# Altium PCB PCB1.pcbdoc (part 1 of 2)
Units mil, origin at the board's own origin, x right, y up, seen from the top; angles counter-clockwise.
Board outline 29590.16 x 26896.25 mil, 2 copper layers (Top Layer, Bottom Layer); 414 components, 328 nets, 1399 pads, 0 vias.
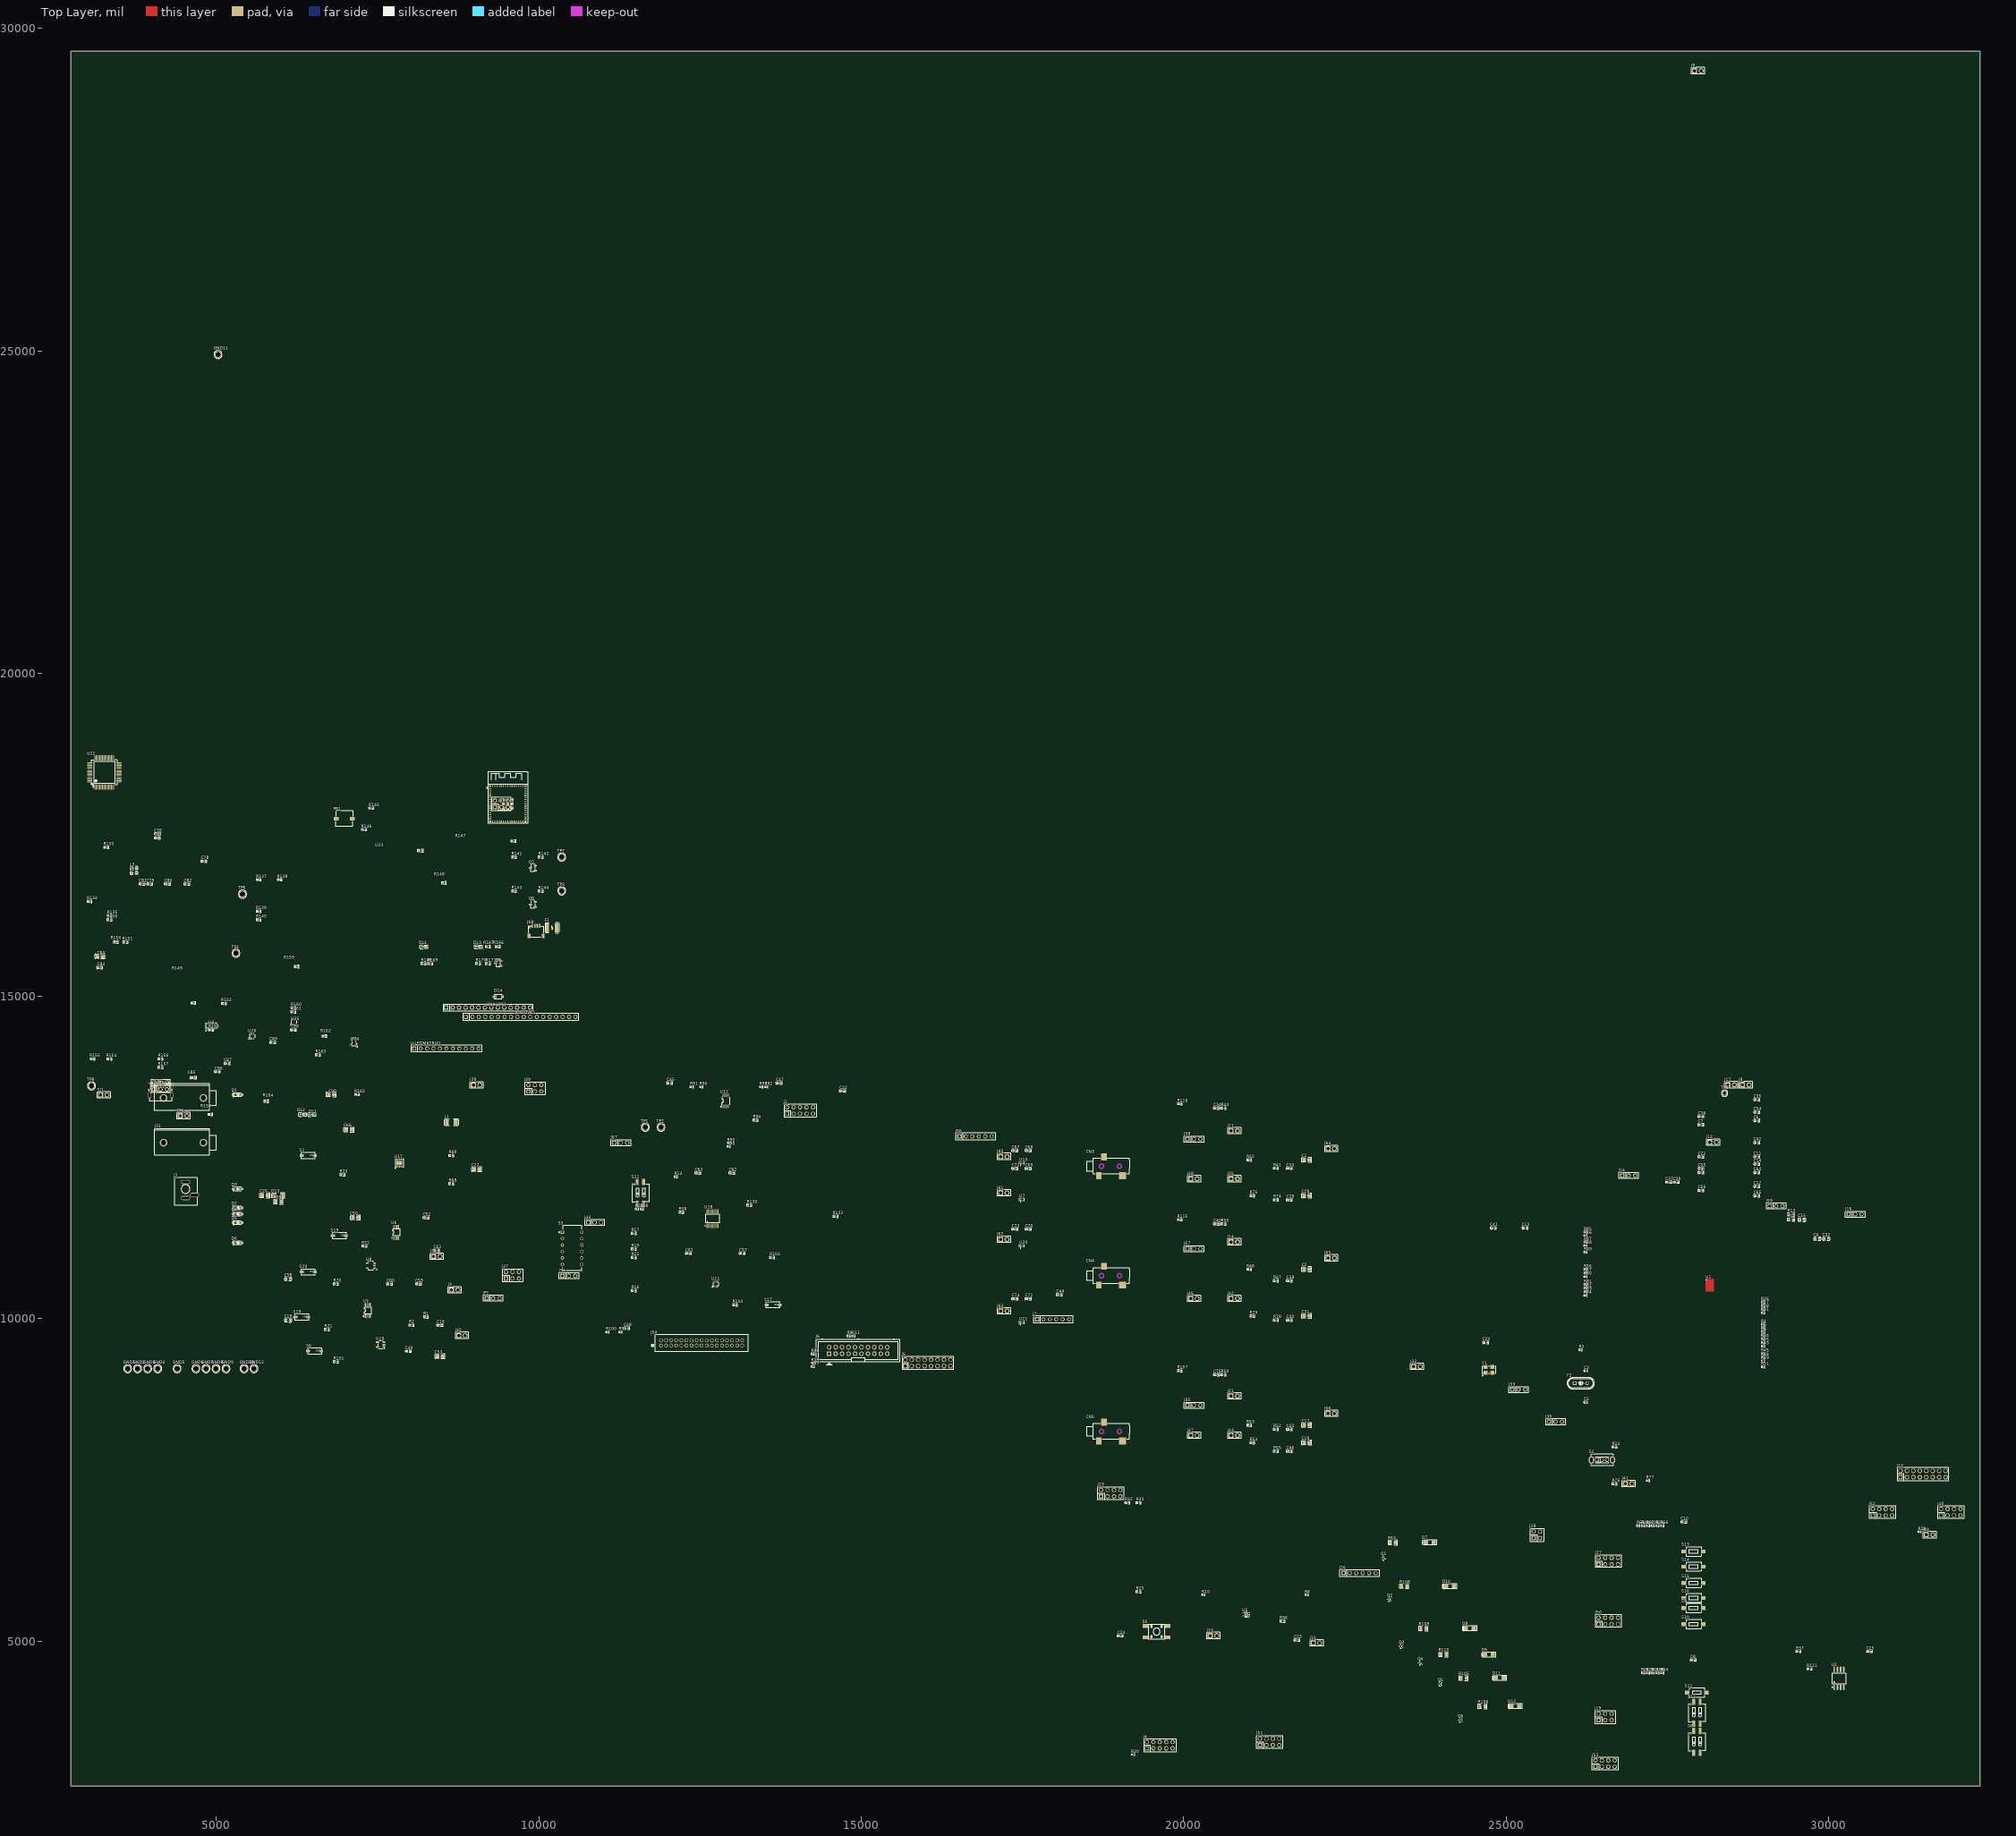
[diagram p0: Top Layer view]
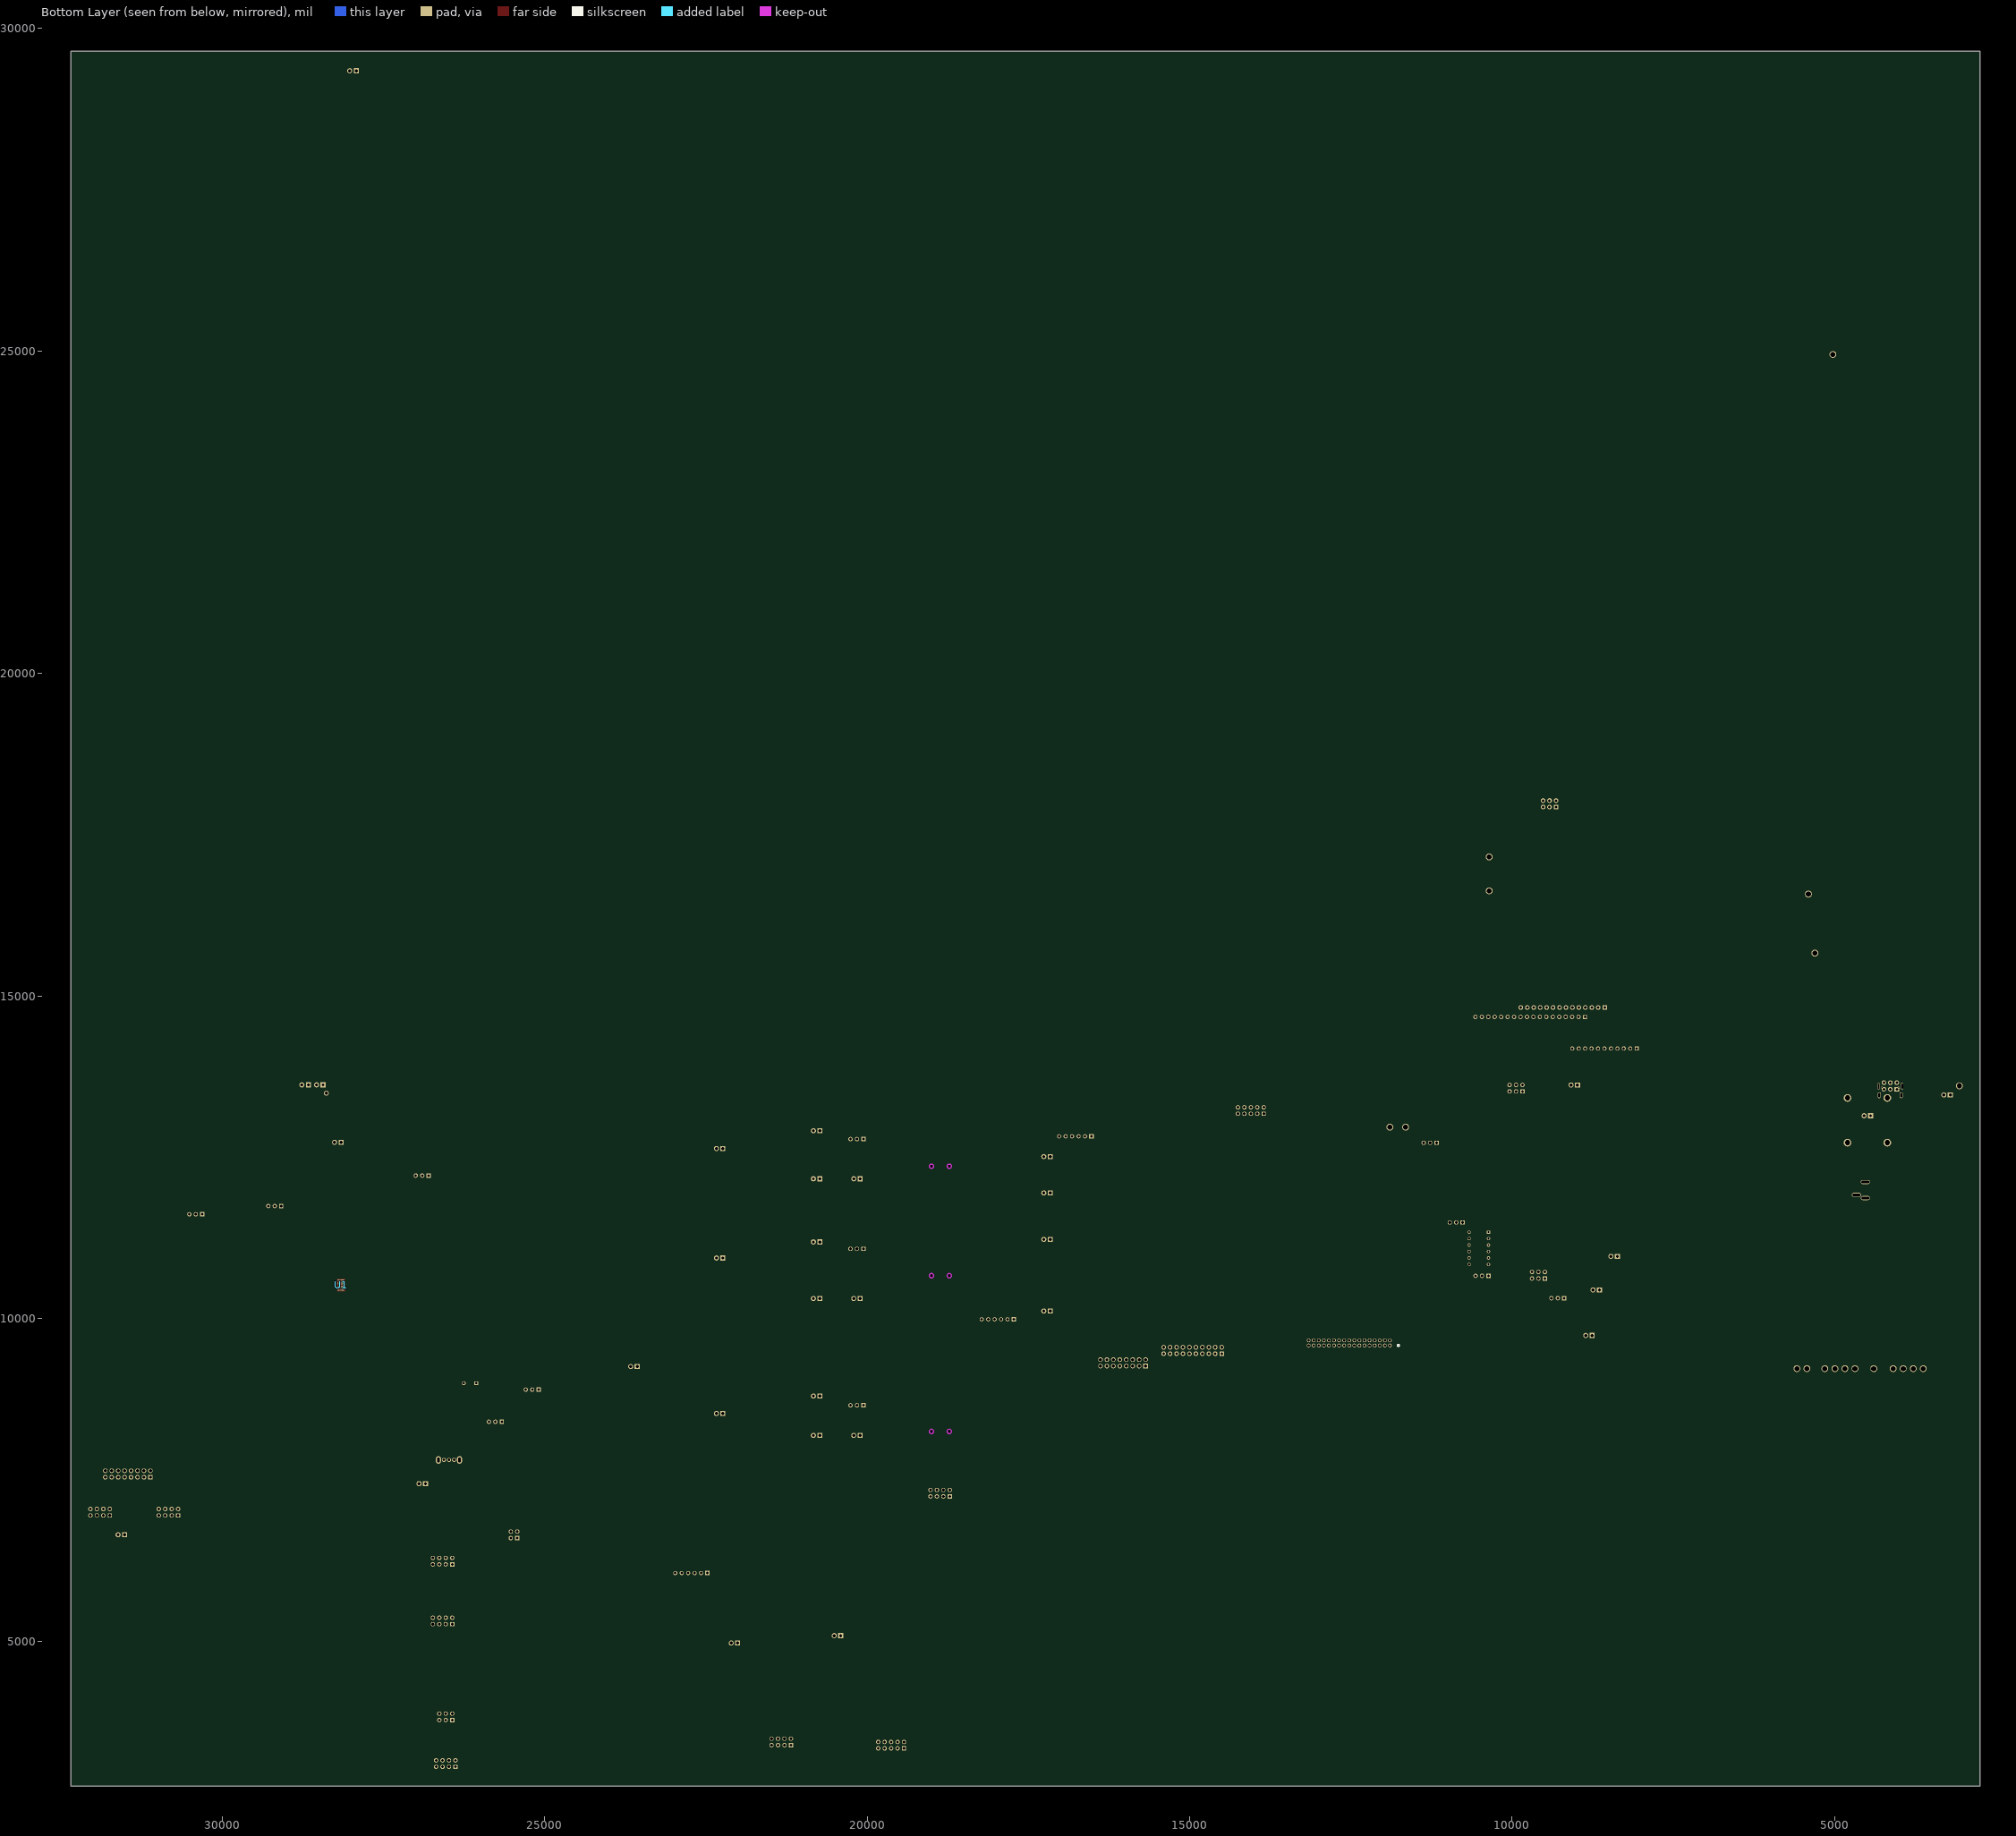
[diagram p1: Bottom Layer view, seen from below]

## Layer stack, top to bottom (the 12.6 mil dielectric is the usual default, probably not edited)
Top Layer: signal copper (thickness not stored)
Dielectric: dielectric 12.6, FR-4, Dk 4.8
Bottom Layer: signal copper (thickness not stored)

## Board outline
32340.16,2750 2750,2750 2750,29646.25 32340.16,29646.25

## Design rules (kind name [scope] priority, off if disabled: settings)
BoardOutlineClearance copperThickness1oz [All] p0: genericclearance=10 ignorepadtopadclearanceinfootprint=FALSE except(0: Arc-SplitContinuation Track-SplitContinuation SMDPad-SplitContinuation THPad-SplitContinuation Via-SplitContinuation Fill-SplitContinuation Poly-SplitContinuation Region-SplitContinuation Text-SplitContinuation; 6: Track-CutoutEdge SMDPad-CutoutEdge THPad-CutoutEdge Via-CutoutEdge Region-CutoutEdge; 11.8: Track-OutlineEdge SMDPad-OutlineEdge THPad-OutlineEdge Via-OutlineEdge Fill-OutlineEdge Region-OutlineEdge Poly-OutlineEdge Text-OutlineEdge Fill-CutoutEdge)
BoardOutlineClearance copperThickness2oz [All] p0: genericclearance=10 ignorepadtopadclearanceinfootprint=FALSE except(0: Arc-SplitContinuation Track-SplitContinuation SMDPad-SplitContinuation THPad-SplitContinuation Via-SplitContinuation Fill-SplitContinuation Poly-SplitContinuation Region-SplitContinuation Text-SplitContinuation; 6: Track-CutoutEdge SMDPad-CutoutEdge THPad-CutoutEdge Via-CutoutEdge Region-CutoutEdge; 11.8: Track-OutlineEdge SMDPad-OutlineEdge THPad-OutlineEdge Via-OutlineEdge Fill-OutlineEdge Region-OutlineEdge Poly-OutlineEdge Text-OutlineEdge Fill-CutoutEdge)
Clearance copperThickness1oz [(InNet('GND') OR InNet('+4V5') OR InNet('+3V3') OR InNet('RESET') OR InNet('P300_SWCLK') OR InNet('P108_SWDIO') OR InNet('RA4_P') OR InNet('RA4_N') OR InNet('P212') OR InNet('P213') OR InNet('P408') OR InNet('P000_AN00_AMP+') OR InNet('P001_AN01_AMP-') OR InNet('P002_AN02_AMPO') OR InNet('P003') OR InNet('P004') OR InNet('P011') OR InNet('P012') OR InNet('P013') OR InNet('P014_AN09_DAC') OR InNet('P015') OR InNet('P502_SCI1_RXD') OR InNet('P501_SCI1_TXD') OR InNet('P100_AN22_SCL') OR InNet('P101_AN21_SDA') OR InNet('P102_SPI0_RSPCK_GPT2_B_CAN0_RX') OR InNet('P103_SPI0_SSL_GPT2_A_CAN0_TX') OR InNet('P104_IRQ01_GPT1_B') OR InNet('P105_IRQ00_GPT1_A') OR InNet('P106_GPT0_B') OR InNet('P107_GPT0_A') OR InNet('P112_GPT3_B') OR InNet('P111_GPT3_A') OR InNet('P110_SCI9_RXD') OR InNet('P109_SCI9_TXD') OR InNet('P301_SCI2_RXD') OR InNet('P302_SCI2_TXD') OR InNet('P303_GPT7_B') OR InNet('P304_GPT7_A') OR InNet('MD') OR InNet('P204') OR InNet('P205') OR InNet('P206') OR InNet('P410_SPI0_MISO_GPT6_B') OR InNet('P411_SPI0_MOSI_GPT6_A') OR InNet('P401_IIC0_SDA') OR InNet('P400_IIC0_SCL') OR InNet('SHIELD1') OR InNet('VUSB') OR InNet('+3V3_I2C') OR InNet('CC1') OR InNet('USB_D_P') OR InNet('USB_D_N') OR InNet('CC2') OR InNet('EXT_SCL') OR InNet('EXT_SDA') OR InNet('ESP_RXD0') OR InNet('ESP_DOWNLOAD') OR InNet('ESP_TXD0') OR InNet('ESP_IO41') OR InNet('ESP_IO42') OR InNet('AREF') OR InNet('ESP_IO4') OR InNet('ESP_IO5') OR InNet('ESP_IO6') OR InNet('ESP_IO7') OR InNet('ESP_IO8') OR InNet('ESP_IO9') OR InNet('ESP_N') OR InNet('ESP_P') OR InNet('ESP_MTCK') OR InNet('ESP_MTDO') OR InNet('ESP32_ENABLE') OR InNet('$4N19647') OR InNet('$4N19643') OR InNet('$4N19648') OR InNet('$4N19492') OR InNet('$4N19507') OR InNet('$4N19510') OR InNet('$4N19539') OR InNet('$4N19549') OR InNet('$4N19548') OR InNet('$4N19290') OR InNet('$4N19293') OR InNet('$4N19297') OR InNet('$4N19298') OR InNet('$4N19649') OR InNet('$4N19292') OR InNet('$4N19362') OR InNet('$4N19317') OR InNet('$4N19314') OR InNet('$4N19653') OR InNet('$4N19546') OR InNet('$4N19547') OR InNet('$4N19383') OR InNet('IOVDD') OR InNet('IOVDD_1797') OR InNet('$4N19372') OR InNet('$1N15076') OR InNet('$1N14795') OR InNet('$1N15959') OR InNet('$1N15937') OR InNet('$1N8935') OR InNet('$1N11460') OR InNet('$1N8973') OR InNet('DVDD') OR InNet('$1N2920') OR InNet('AVDD_1797') OR InNet('HPVDD_1797') OR InNet('$1N10228') OR InNet('$1N11465') OR InNet('DVDD_REG') OR InNet('$1N16782') OR InNet('$1N16760') OR InNet('AIN2-') OR InNet('$1N16771') OR InNet('+5V_AARDVARK') OR InNet('PD') OR InNet('$1N17614') OR InNet('+1V8_REG_SW') OR InNet('$1N14914') OR InNet('AIN0-') OR InNet('$1N15948') OR InNet('AIN1-') OR InNet('+1V8') OR InNet('CP1-') OR InNet('CP1+') OR InNet('CP2-') OR InNet('CP2+') OR InNet('+5V_UART') OR InNet('$3N8981') OR InNet('$3N8977') OR InNet('+1V8_REG_LIN') OR InNet('$3N5510') OR InNet('+1V2') OR InNet('$3N5995') OR InNet('$1N14654') OR InNet('$1N14540') OR InNet('$1N15927') OR InNet('$1N15923') OR InNet('$1N16750') OR InNet('$1N16746') OR InNet('+5V_EXT') OR InNet('$3N506') OR InNet('+5V_PROMIRA') OR InNet('+5V_JTAG') OR InNet('$1N21553') OR InNet('$1N20491') OR InNet('$1N20961') OR InNet('$1N21374') OR InNet('$1N20676') OR InNet('$1N21381') OR InNet('$1N21388') OR InNet('$3N1554') OR InNet('SCL_USB') OR InNet('SDA_USB') OR InNet('MISO_USB') OR InNet('BRD_RESET') OR InNet('SCLK_USB') OR InNet('MOSI_USB') OR InNet('SS_USB') OR InNet('$3N8455') OR InNet('SDATAI_1/MP5') OR InNet('BCLK_1/MP6') OR InNet('SDATAO_1/MP4') OR InNet('FSYNC_1/MP7') OR InNet('$1N20097') OR InNet('SDA1') OR InNet('SCL1') OR InNet('JTAG_TRST/MP22') OR InNet('JTAG_TDI/MP25') OR InNet('JTAG_TMS/MP23') OR InNet('JTAG_TCK/MP24') OR InNet('$2N10821') OR InNet('JTAG_TDO/MP26') OR InNet('$2N10823') OR InNet('$2N10825') OR InNet('CTS_UART') OR InNet('TXD_UART') OR InNet('RXD_UART') OR InNet('RTS_UART') OR InNet('$1N17731') OR InNet('$1N17727') OR InNet('$1N14477') OR InNet('DMIC_CLK1/MP14') OR InNet('DMIC_CLK0/MP13') OR InNet('DMIC67/MP11') OR InNet('DMIC89/MP12') OR InNet('DMIC45/MP10') OR InNet('DMIC23/MP9') OR InNet('DMIC01/MP8') OR InNet('$1N15921') OR InNet('$1N24995') OR InNet('$1N25008') OR InNet('$1N25013') OR InNet('$1N16744') OR InNet('TEST1') OR InNet('TEST2') OR InNet('TEST0') OR InNet('TEST_EN') OR InNet('REG_EN') OR InNet('$1N14235') OR InNet('$1N21426') OR InNet('$1N21420') OR InNet('$1N21412') OR InNet('$1N21405') OR InNet('$1N21398') OR InNet('$1N20304') OR InNet('SDATAO_0/MP0') OR InNet('$1N23160') OR InNet('SDATAI_0/MP1') OR InNet('$1N23619') OR InNet('FSYNC_0/MP3') OR InNet('$1N23625') OR InNet('BCLK_0/MP2') OR InNet('$1N23631') OR InNet('$3N4842') OR InNet('MCLK_IN') OR InNet('XTALI') OR InNet('$1N8528') OR InNet('OSC') OR InNet('EXT_MCLK') OR InNet('SDA_PROMIRA') OR InNet('SDA_0/MISO') OR InNet('$2N8118') OR InNet('IOVDD_EXT') OR InNet('$1N8257') OR InNet('$1N15904') OR InNet('$1N16727') OR InNet('SCL_PROMIRA') OR InNet('SCL_0/SCLK') OR InNet('$2N8059') OR InNet('$1N19695') OR InNet('$1N24875') OR InNet('$1N23637') OR InNet('$1N23643') OR InNet('$1N24884') OR InNet('QSPIM_SDIO_1/MP19') OR InNet('QSPIM_CLK/MP15') OR InNet('QSPIM_SDIO_0/MP18') OR InNet('QSPIM_CS0/MP16') OR InNet('QSPIM_SDIO_2/MP20') OR InNet('QSPIM_SDIO_3/MP21') OR InNet('QSPIM_CS1/MP17') OR InNet('IOVDD_PROMIRA') OR InNet('$1N16740') OR InNet('UART_RTS/MP29') OR InNet('UART_RX/MP28') OR InNet('UART_TX/MP27') OR InNet('UART_CTS/MP30') OR InNet('$1N15917') OR InNet('$1N14294') OR InNet('$1N11410') OR InNet('$1N11371') OR InNet('$2N14979') OR InNet('$2N15027') OR InNet('$2N15536') OR InNet('$2N15539') OR InNet('AIN0+') OR InNet('AIN1+') OR InNet('AIN2+') OR InNet('SCL_1797') OR InNet('SDA_1797') OR InNet('$3N4375') OR InNet('$1N20401') OR InNet('$1N20673') OR InNet('$1N20958') OR InNet('$1N21371') OR InNet('$1N21378') OR InNet('$1N21385') OR InNet('$3N8224') OR InNet('XTALO') OR InNet('FSYNC_0_1797') OR InNet('BCLK_0_1797') OR InNet('SDATAI_0_1797') OR InNet('SDATAO_0_1797') OR InNet('$2N7921') OR InNet('SPI_MISO') OR InNet('$2N7925') OR InNet('SPI_SCLK') OR InNet('$2N7974') OR InNet('ADDR1') OR InNet('SPI_MOSI') OR InNet('$2N7967') OR InNet('SPI_SS') OR InNet('ADDR0') OR InNet('$1N1953') OR InNet('FSYNC_1_1797') OR InNet('BCLK_1_1797') OR InNet('SDATAI_1_1797') OR InNet('SDATAO_1_1797') OR InNet('DMIC_CLK0_1797') OR InNet('DMIC_CLK1_1797') OR InNet('$1N17839') OR InNet('$2N681') OR InNet('DMIC01_1797') OR InNet('DMIC23_1797') OR InNet('DMIC45_1797') OR InNet('DMIC89_1797') OR InNet('DMIC67_1797') OR InNet('QSPIM_CS0_1797') OR InNet('QSPIM_CS1_1797') OR InNet('$3N4489') OR InNet('$3N4413') OR InNet('1715_EN') OR InNet('5335_EN') OR InNet('5302_EN') OR InNet('$1N1981') OR InNet('$1N5576') OR InNet('QSPIM_CLK_1797') OR InNet('QSPIM_SDIO_0_1797') OR InNet('QSPIM_SDIO_1_1797') OR InNet('QSPIM_SDIO_2_1797') OR InNet('QSPIM_SDIO_3_1797') OR InNet('JTAG_TDO_1797') OR InNet('JTAG_TRST_1797') OR InNet('JTAG_TCK_1797') OR InNet('JTAG_TMS_1797') OR InNet('JTAG_TDI_1797') OR InNet('$2N1616') OR InNet('DBGRQ') OR InNet('RTCK') OR InNet('$3N8798') OR InNet('MASTER_SLAVE_SEL') OR InNet('$1N18363') OR InNet('$2N697') OR InNet('ADDR0/SS') OR InNet('ADDR1/MOSI'))] p1: gap=7 ignorepadtopadclearanceinfootprint=FALSE except(4: Track-Track; 6: Track-SMDPad SMDPad-SMDPad Track-THPad SMDPad-THPad THPad-THPad Track-Via SMDPad-Via THPad-Via Via-Via SMDPad-Fill THPad-Fill Via-Fill Fill-Fill Track-Region SMDPad-Region THPad-Region Via-Region Region-Region Track-Poly SMDPad-Poly THPad-Poly Via-Poly Fill-Poly Region-Poly Poly-Poly Track-Text SMDPad-Text THPad-Text Via-Text Fill-Text Region-Text Poly-Text Text-Text; 6.9: Track-Hole SMDPad-Hole THPad-Hole Via-Hole Fill-Hole Region-Hole Poly-Hole Text-Hole Sheet-Hole; 11.8: Track-Fill Fill-Region Track-Sheet SMDPad-Sheet THPad-Sheet Via-Sheet Fill-Sheet Region-Sheet Poly-Sheet Text-Sheet)
Clearance copperThickness2oz [All] p1: gap=7 ignorepadtopadclearanceinfootprint=FALSE except(6: Track-SMDPad SMDPad-SMDPad Track-THPad SMDPad-THPad THPad-THPad Track-Via SMDPad-Via THPad-Via Via-Via SMDPad-Fill THPad-Fill Via-Fill Fill-Fill Track-Region SMDPad-Region THPad-Region Via-Region Region-Region Track-Poly SMDPad-Poly THPad-Poly Via-Poly Fill-Poly Region-Poly Poly-Poly Track-Text SMDPad-Text THPad-Text Via-Text Fill-Text Region-Text Poly-Text Text-Text; 6.9: Track-Hole SMDPad-Hole THPad-Hole Via-Hole Fill-Hole Region-Hole Poly-Hole Text-Hole Sheet-Hole; 8: Track-Track; 11.8: Track-Fill Fill-Region Track-Sheet SMDPad-Sheet THPad-Sheet Via-Sheet Fill-Sheet Region-Sheet Poly-Sheet Text-Sheet)
DiffPairsRouting differentialPair [All] p1: maxuncoupledlength=10 minlimit=6 maxlimit=6 mostfreqgap=6 toplayer_minwidth=5 toplayer_prefwidth=10 toplayer_maxwidth=100 bottomlayer_minwidth=5 bottomlayer_prefwidth=10 bottomlayer_maxwidth=100
PasteMaskExpansion pasteMaskExpansion [All] p1: expansion=0
PlaneConnect innerPlane [All] p1: planeconnectstyle=Relief reliefexpansion=20 reliefentries=4 reliefconductorwidth=10 reliefairgap=10
PolygonConnect copperRegion [All] p1: connectstyle=Relief reliefentries=4 reliefconductorwidth=10 polygonreliefangle="90 Angle" airgapwidth=10
RoutingVias viaSize [All] p1: viastyle="Through Hole" holewidth=12.0078 minholewidth=11.811 maxholewidth=248.0314 width=24.0158 minwidth=19.685 maxwidth=393.7008
SolderMaskExpansion solderMaskExpansion [All] p1: useseparateexpansions=TRUE expansion=2 expansionbottom=2
Width copperThickness1oz [All] p1: maxlimit=100 minlimit=5 preferedwidth=10
Width copperThickness2oz [All] p1: maxlimit=100 minlimit=8 preferedwidth=10

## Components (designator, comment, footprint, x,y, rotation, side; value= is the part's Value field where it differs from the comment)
C1 "CS2012X7R106M100NRE" C0805 21906.44,12462.24 r0 top
C2 "CS2012X7R106M100NRE" C0805 21906.44,10765.39 r0 top
C3 "GRM0335C1H300GA01D" C0201 26231.69,9194.72 r0 top
C4 "CGA0603X5R105K500JT" C0603 29821.36,11238.37 r0 top
C5 "GRM0335C1H300GA01D" C0201 26231.69,8706.05 r0 top
C6 "FCC0402B104K160AT" C0402 28884.25,13072.18 r0 top
C7 "FCC0402B104K160AT" C0402 28020.13,13007.24 r0 top
C8 "FCC0402B104K160AT" C0402 27902.42,4710.33 r0 top
C9 "FCC0402B104K160AT" C0402 28020.13,12267.4 r0 top
C10 "FCC0402B104K160AT" C0402 27752.42,6851.05 r0 top
C11 "FCC0402B104K160AT" C0402 28884.25,12512.24 r0 top
C12 "FCC0402B104K160AT" C0402 28884.25,12052.46 r0 top
C13 "FCC0402B104K160AT" C0402 25291,11405.5 r0 top
C14 "FCC0402B104K160AT" C0402 28884.25,12397.29 r0 top
C15 "CGA0603X5R105K500JT" C0603 29582.2,11535.39 r0 top
C16 "GRM155R70J105KA12D" C0402 8469.12,9899.82 r0 top
C17 "CS2012X7R106M100NRE" C0805 21906.44,8350.25 r0 top
C18 "GRM188R71C105KA12D" C0603 6114.87,9975.09 r0 top
C19 "CS2012X7R106M100NRE" C0805 21906.44,8076.73 r0 top
C20 "FCC0402B104K160AT" C0402 24681.81,9629.68 r0 top
C21 "FCC0402B104K160AT" C0402 28020.13,12512.24 r0 top
C22 "FCC0402B104K160AT" C0402 14711.46,13532.89 r0 top
C23 "GRM155R71C104KA88D" C0402 21757.43,5019.66 r0 top
C24 "GRM155R71C104KA88D" C0402 19017.51,5084.6 r0 top
C25 "FCC0402B104K160AT" C0402 30630.63,4841.75 r0 top
C26 "CL21A106KPFNNNE" C0805 5754.04,11909.89 r0 top
C27 "CL21B106KPQNNNE" C0805 9037.36,12314.03 r0 top
C28 "FCC0402B104K160AT" C0402 21639.72,11841.68 r0 top
C29 "CS2012X7R106M100NRE" C0805 21906.44,11906.62 r0 top
C30 "FCC0402B104K160AT" C0402 21639.72,9976.83 r0 top
C31 "CS2012X7R106M100NRE" C0805 21906.44,10041.77 r0 top
C32 "CGA0603X5R105K500JT" C0603 29960.49,11238.37 r0 top
C33 "FCC0402B104K160AT" C0402 21639.72,12332.35 r0 top
C34 "CC0402KRX7R5BB105_C115046" C0402 20509.5,13267.02 r0 top
C35 "FCC0402B104K160AT" C0402 28884.25,13396.91 r0 top
C36 "FCC0402B104K160AT" C0402 28020.13,13137.13 r0 top
C37 "0402X7R104K500NT" C0402 27517,12117.4 r0 top
C38 "FCC0402B104K160AT" C0402 21639.72,10591.11 r0 top
C39 "0402X7R104K500NT" C0402 27634.71,12117.4 r0 top
C40 "CC0402KRX7R5BB105_C115046" C0402 20509.5,11470.44 r0 top
C41 "FCC0402B104K160AT" C0402 24799.52,11405.5 r0 top
C42 "FCC0402B104K160AT" C0402 28884.25,12733.03 r0 top
C43 "FCC0402B104K160AT" C0402 21639.72,8285.31 r0 top
C44 "FCC0402B104K160AT" C0402 18072.87,10373.49 r0 top
C45 "FCC0402B104K160AT" C0402 12031.98,13654.28 r0 top
C46 "FCC0402B104K160AT" C0402 21639.72,7946.84 r0 top
C47 "FCC0402B104K160AT" C0402 13727.12,13654.28 r0 top
C48 "FCC0402B104K160AT" C0402 11367.53,9853.44 r0 top
C49 "0402B103K250NT" C0402 7978.68,9496.53 r0 top
C50 "CL21A106KPFNNNE" C0805 7158.52,11568.35 r0 top
C51 "CC0402KRX7R5BB105_C115046" C0402 8419.12,11061.33 r0 top
C52 "GRM1555C1H102JA01D" C0402 8255.26,11568.35 r0 top
C53 "CL21B106KPQNNNE" C0805 8469.12,9415.64 r0 top
C54 "FCC0402B104K160AT" C0402 28884.25,13202.07 r0 top
C55 "FCC0402B104K160AT" C0402 28020.13,12332.35 r0 top
C56 "FCC0402B104K160AT" C0402 28020.13,11987.51 r0 top
C57 "GRM155R71C104KA88D" C0402 13156.01,11014.49 r0 top
C58 "GRM188R71C105KA12D" C0603 6114.87,10616.52 r0 top
C59 "GRM155R70J105KA12D" C0402 8137.56,10541.25 r0 top
C60 "0402B103K250NT" C0402 7689.99,10541.25 r0 top
C61 "GRM155R71C104KA88D" C0402 12324.37,11014.49 r0 top
C62 "GRM155R71C104KA88D" C0402 12997.14,12262.52 r0 top
C63 "GRM155R71C104KA88D" C0402 12470.54,12262.52 r0 top
C64 "FCC0402B104K160AT" C0402 28884.25,12267.4 r0 top
C65 "FCC0402B104K160AT" C0402 28884.25,11906.62 r0 top
C66 "CL21A106KPFNNNE" C0805 7058.52,12928.15 r0 top
C67 "FCC0402B104K160AT" C0402 17382.85,12608.78 r0 top
C68 "FCC0402B104K160AT" C0402 17589.33,12608.78 r0 top
C69 "FCC0402B104K160AT" C0402 17589.33,12327.47 r0 top
C70 "FCC0402B104K160AT" C0402 17589.33,11390.07 r0 top
C71 "FCC0402B104K160AT" C0402 17589.33,10308.54 r0 top
C72 "FCC0402B104K160AT" C0402 17382.85,12327.47 r0 top
C73 "FCC0402B104K160AT" C0402 17382.85,11390.07 r0 top
C74 "FCC0402B104K160AT" C0402 17382.85,10308.54 r0 top
C75 "CC0402KRX7R5BB105_C115046" C0402 20509.5,9134.02 r0 top
C76 "CL05A105KP5NNNC" C0402 4087.03,17518.07 r0 top
C77 "GRM155R61H104KE19D" C0402 4087.03,17453.12 r0 top
C78 "CL05A105KP5NNNC" C0402 4811.69,17091.65 r0 top
C79 "GRM155R61H104KE19D" C0402 3969.32,16742.06 r0 top
C80 "GRM155R61H104KE19D" C0402 4245.91,16742.06 r0 top
C81 "CL05A105KP5NNNC" C0402 3851.62,16742.06 r0 top
C82 "CL05A105KP5NNNC" C0402 4548,16742.06 r0 top
C83 "CL21A226MAQNNNE" C0805 3197.05,15615.93 r0 top
C84 "GRM155R61H104KE19D" C0402 3197.05,15443.44 r0 top
C85 "GRM155R61H104KE19D" C0402 4648,13734.01 r0 top
C86 "GRM155R61H104KE19D" C0402 5020.6,13831.44 r0 top
C87 "CL05A105KP5NNNC" C0402 5170.63,13961.33 r0 top
C88 "GRM155R61H104KE19D" C0402 6199.87,14476.77 r0 top
C89 "GRM155R61H104KE19D" C0402 5877.6,14284.28 r0 top
C90 "FV21X472K102ECG" C0805 6785.91,13476.8 r0 top
CN3 "SJ-3523-SMT-TR_C4991872" AUDIO-SMD_SJ-3523-SMT-TR 18867.51,12362.24 r0 top
CN4 "SJ-3523-SMT-TR_C4991872" AUDIO-SMD_SJ-3523-SMT-TR 18867.51,10665.39 r0 top
CN5 "SJ-3523-SMT-TR_C4991872" AUDIO-SMD_SJ-3523-SMT-TR 18867.51,8250.25 r0 top
D1 "MBR0530T1G" SOD-123_L2.7-W1.6-LS3.7-RD-1 5330.4,13471.91 r0 top
D2 "MBR0530T1G" SOD-123_L2.7-W1.6-LS3.7-RD-1 5330.4,11715.17 r0 top
D3 "MBR0530T1G" SOD-123_L2.7-W1.6-LS3.7-RD-1 5330.4,12012.03 r0 top
D4 "MBR0530T1G" SOD-123_L2.7-W1.6-LS3.7-RD-1 5330.4,11618.35 r0 top
D5 "MBR0530T1G" SOD-123_L2.7-W1.6-LS3.7-RD-1 5330.4,11487.47 r0 top
D6 "MBR0530T1G" SOD-123_L2.7-W1.6-LS3.7-RD-1 5330.4,11176.27 r0 top
D7 "LTST-C150KRKT" LED1206-RD 23814.38,6528.53 r0 top
D8 "LTST-C150KRKT" LED1206-RD 24435.65,5197.39 r0 top
D9 "LTST-C150KRKT" LED1206-RD 24731.81,4791.75 r0 top
D10 "LTST-C150KRKT" LED1206-RD 24125.02,5850.57 r0 top
D11 "LTST-C150KRKT" LED1206-RD 24899.52,4427.95 r0 top
D12 "LTST-C150KRKT" LED1206-RD 25141,3989.67 r0 top
D13 "LED_GREEN" LED1206-R-RD_GREEN 5963.13,11909.89 r0 top
D14 "PMEG6020AELRX" SOD-123_L2.6-W1.7-LS3.5-RD 9370.12,14992.18 r0 top
DL1 "VFHL1116P-4BX3C-TR" LED-SMD_L1.6-W0.8-RD 6480.21,13164.77 r0 top
DL2 "VFHL1116P-4BX3C-TR" LED-SMD_L1.6-W0.8-RD 6340.04,13164.77 r0 top
DL3 "HSMG-C190" LED-SMD_L1.6-W0.8-R-RD 9061.09,15765.93 r0 top
DL4 "VFHL1116P-4BX3C-TR" LED-SMD_L1.6-W0.8-RD 8218.51,15765.93 r0 top
F1 "MF-MSMF050-2" F1812 10206.15,16060.84 r0 top
GND1 "RH-5011" TESTPOINT-TH_BD3.2 3626.51,9224.45 r0 top
GND2 "RH-5011" TESTPOINT-TH_BD3.2 3782.17,9224.45 r0 top
GND3 "RH-5011" TESTPOINT-TH_BD3.2 3937.84,9224.45 r0 top
GND4 "RH-5011" TESTPOINT-TH_BD3.2 4093.5,9224.45 r0 top
GND5 "RH-5011" TESTPOINT-TH_BD3.2 4393.5,9224.45 r0 top
GND6 "RH-5011" TESTPOINT-TH_BD3.2 4685.18,9224.45 r0 top
GND7 "RH-5011" TESTPOINT-TH_BD3.2 4840.84,9224.45 r0 top
GND8 "RH-5011" TESTPOINT-TH_BD3.2 4996.51,9224.45 r0 top
GND9 "RH-5011" TESTPOINT-TH_BD3.2 5152.17,9224.45 r0 top
GND10 "RH-5011" TESTPOINT-TH_BD3.2 5430.4,9224.45 r0 top
GND11 "RH-5011" TESTPOINT-TH_BD3.2 5027.55,24947.79 r0 top
GND12 "RH-5011" TESTPOINT-TH_BD3.2 5586.06,9224.45 r0 top
J1 "HEADER_10WAY_POL" HDR-TH_10P-P2.54-V-M-R2-C5-S2.54 14050.82,13225.42 r0 top
J2 "EXT_5V" DC-IN-TH_DC-509-ARL200-H142 4593.5,11992.91 r0 top
J3 "1.8V EXT" HDR-TH_2P-P2.54-V-M 8695.81,10444.94 r0 top
J4 "PZ254V-12-10P" HDR-TH_10P-P2.54-V-M-R2-C5-S2.54 19627.45,3386.91 r0 top
J5 "HEADER_16WAY_UNSHROUD" HDR-TH_16P-P2.54-V-M-R2-C8-S2.54 16032.1,9313.7 r0 top
J6 "N2520-6002-RB" IDC-TH_20P-P2.54_3M_N2520-6002-RB 14952.59,9505.18 r0 top
J7 "2.54-1*6P母" HDR-TH_6P-P2.54-V-F 17972.87,9989.06 r0 top
J8 "IOVDD_1797" HDR-TH_2P-P2.54-V-M 27969.9,29346.25 r0 top
J9 "HPVDD_1797" HDR-TH_2P-P2.54-V-M 28711.56,13622.91 r0 top
J10 "PZ254V-11-02P" HDR-TH_2P-P2.54-V-M 20459.5,5084.6 r0 top
J11 "PZ254V-11-02P" HDR-TH_2P-P2.54-V-M 20782.23,12910.92 r0 top
J12 "DVDD" HDR-TH_2P-P2.54-V-M 28205.19,12733.03 r0 top
J13 "PZ254V-12-16P" HDR-TH_16P-P2.54-V-M-R2-C8-S2.54 31460.31,7590.31 r0 top
J14 "PZ254V-11-02P" HDR-TH_2P-P2.54-V-M 20782.23,11188.37 r0 top
J15 "PZ254V-11-02P" HDR-TH_2P-P2.54-V-M 22057.6,4969.66 r0 top
J16 "PZ254V-11-03P" HDR-TH_3P-P2.54-V-M 30406.93,11617.04 r0 top
J17 "AVDD_1797" HDR-TH_2P-P2.54-V-M 28483.87,13622.91 r0 top
J19 "PZ254V-12-6P" HDR-TH_6P-P2.54-V-M-R2-C3-S2.54 26531.61,3825.88 r0 top
J21 "PZ254V-11-02P" HDR-TH_2P-P2.54-V-M 20782.23,8798.11 r0 top
J23 "PZ254V-12-8P" HDR-TH_8P-P2.54-V-M-R2-C4-S2.54 18867.51,7293 r0 top
J24 "PZ254V-11-03P" HDR-TH_3P-P2.54-V-M 26896.47,12217.4 r0 top
J25 "PZ254V-11-02P" HDR-TH_2P-P2.54-V-M 20782.23,12167.4 r0 top
J26 "2.54-1*6P母" HDR-TH_6P-P2.54-V-F 22723.81,6054.47 r0 top
J27 "PZ254V-12-8P" HDR-TH_8P-P2.54-V-M-R2-C4-S2.54 26581.61,6239.74 r0 top
J28 "PZ254V-12-4P" HDR-TH_4P-P2.54-V-M-R2-C2-S2.54 25473.75,6647.3 r0 top
J29 "1.8V EXT" HDR-TH_2P-P2.54-V-M 9037.36,13621.91 r0 top
J30 "PZ254V-11-03P" HDR-TH_3P-P2.54-V-M 25762.49,8400.25 r0 top
J31 "GND" CONN-TH_24.243.2 4493.5,12728.15 r0 top
J32 "EXT_OSC_DISABLE" HDR-TH_2P-P2.54-V-M 23614.38,9255.41 r0 top
J33 "PZ254V-11-03P" HDR-TH_3P-P2.54-V-M 25191,8898.11 r0 top
J34 "PZ254V-11-03P" HDR-TH_3P-P2.54-V-M 10466.8,10663.67 r0 top
J35 "IOVDD_EXT_IN" HDR-TH_2P-P2.54-V-M 8419.12,10965.01 r0 top
J36 "EXT_OSC_DISABLE" HDR-TH_2P-P2.54-V-M 4493.5,13144.41 r0 top
J37 "PZ254V-12-6P" HDR-TH_6P-P2.54-V-M-R2-C3-S2.54 9592.35,10672.12 r0 top
J38 "+5V" CONN-TH_24.243.1_RED 4493.5,13421.91 r0 top
J39 "PZ254V-12-6P" HDR-TH_6P-P2.54-V-M-R2-C3-S2.54 9940.15,13571.91 r0 top
J40 "PZ254V-12-8P" HDR-TH_8P-P2.54-V-M-R2-C4-S2.54 31890.16,6998.37 r0 top
J41 "OSC_OUT" HDR-TH_2P-P2.54-V-M 26896.47,7440.31 r0 top
J42 "PZ254V-11-02P" HDR-TH_2P-P2.54-V-M 20782.23,10311.1 r0 top
J43 "PZ254V-11-02P" HDR-TH_2P-P2.54-V-M 20782.23,8188.99 r0 top
J44 "PZ254V-11-03P" HDR-TH_3P-P2.54-V-M 10867.03,11490.07 r0 top
J45 "1.8V EXT" HDR-TH_2P-P2.54-V-M 8809.67,9738.56 r0 top
J46 "SE-MODE" HDR-TH_2P-P2.54-V-M 20157.17,10311.1 r0 top
J47 "SE-MODE" HDR-TH_2P-P2.54-V-M 20157.17,8188.99 r0 top
J48 "SE-MODE" HDR-TH_2P-P2.54-V-M 20157.17,12167.4 r0 top
J49 "DVDD" HDR-TH_2P-P2.54-V-M 31561.47,6647.3 r0 top
J50 "PZ254V-12-8P" HDR-TH_8P-P2.54-V-M-R2-C4-S2.54 26581.61,5312.82 r0 top
J51 "PZ254V-12-8P" HDR-TH_8P-P2.54-V-M-R2-C4-S2.54 21330.82,3436.91 r0 top
J52 "PZ254V-12-8P" HDR-TH_8P-P2.54-V-M-R2-C4-S2.54 30830.63,6998.37 r0 top
J53 "PZ254V-12-8P" HDR-TH_8P-P2.54-V-M-R2-C4-S2.54 26531.61,3100.79 r0 top
J54 "HDR_2X17WAY_2MM_POL" CONN34_878313420_MOL 11895.3,9583.29 r0 top
J55 "PZ254V-11-03P" HDR-TH_3P-P2.54-V-M 20157.17,8656.05 r0 top
J56 "2.54-1*6P母" HDR-TH_6P-P2.54-V-F 16771.62,12825.91 r0 top
J57 "PZ254V-11-03P" HDR-TH_3P-P2.54-V-M 20157.17,11081.92 r0 top
J58 "PZ254V-11-03P" HDR-TH_3P-P2.54-V-M 20157.17,12783.03 r0 top
J59 "PZ254V-11-03P" HDR-TH_3P-P2.54-V-M 29182.59,11745.15 r0 top
J60 "EXT_OSC_DISABLE" HDR-TH_2P-P2.54-V-M 17210.15,12512.46 r0 top
J61 "EXT_OSC_DISABLE" HDR-TH_2P-P2.54-V-M 17210.15,11947.23 r0 top
J62 "EXT_OSC_DISABLE" HDR-TH_2P-P2.54-V-M 17210.15,11228.81 r0 top
J63 "EXT_OSC_DISABLE" HDR-TH_2P-P2.54-V-M 17210.15,10116.96 r0 top
J64 "PZ254V-11-02P" HDR-TH_2P-P2.54-V-M 22285.28,12636.71 r0 top
J65 "PZ254V-11-02P" HDR-TH_2P-P2.54-V-M 22285.28,10939.86 r0 top
J66 "PZ254V-11-02P" HDR-TH_2P-P2.54-V-M 22285.28,8528.15 r0 top
J67 "PZ254V-11-03P" HDR-TH_3P-P2.54-V-M 11271.36,12725.91 r0 top
J68 "SM04B-SRSS-TB(LF)(SN)" CONN-SMD_4P-P1.00_SM04B-SRSS-TB-LF-SN 9958.08,16010.84 r0 top
J69 "PH2-06-UA" HDR-TH_6P-P2.54-V-M-R2-C3-S2.54-1 9420.12,17980.81 r0 top
J70 "PH2-06-UA" HDR-TH_6P-P2.54-V-M-R2-C3-S2.54-1 4137.03,13606.69 r0 top
J71 "CX90B-16P" USB-C-SMD_CX90B-16P 4137.03,13541.74 r0 top
JANALOG1 "PZ254-1-14-Z-8.5" HDR-TH_14P-P2.54-V-M 9215.6,14821.83 r0 top
JDIGITAL1 "PZ254-1-18-Z-8.5" HDR-TH_18P-P2.54-V-M 9720.19,14677.37 r0 top
JP1 "PZ254V-11-03P" HDR-TH_3P-P2.54-V-M 9292.35,10317.04 r0 top
L1 "LQH32PN2R2NN0L" L1210 8645.81,13044.41 r0 top
L2 "BLM18PG471SN1D" L0603 3723.85,16909.33 r0 top
L3 "BLM18PG471SN1D" L0603 3723.85,16986.25 r0 top
M4 "ESP32-S3-MINI-1-N8" BULETM-SMD_ESP32-S3-MINI-1-N8 9520.15,17980.81 r0 top
PB1 "SPEH130103" SW-SMD_L6.0-W6.0-LS6.6 6985.91,17749.44 r0 top
Q1 "DTC114YET1G" SC-75-3_L1.6-W0.8-P1.00-LS1.7-BR 23095.15,6289.74 r0 top
Q2 "DTC114YET1G" SC-75-3_L1.6-W0.8-P1.00-LS1.7-BR 23189.53,5648.09 r0 top
Q3 "DTC114YET1G" SC-75-3_L1.6-W0.8-P1.00-LS1.7-BR 23368.36,4919.66 r0 top
Q4 "DTC114YET1G" SC-75-3_L1.6-W0.8-P1.00-LS1.7-BR 23664.38,4660.33 r0 top
Q5 "DTC114YET1G" SC-75-3_L1.6-W0.8-P1.00-LS1.7-BR 23975.02,4336.17 r0 top
Q6 "DTC114YET1G" SC-75-3_L1.6-W0.8-P1.00-LS1.7-BR 24285.65,3775.88 r0 top
Q7 "2N7002KT1G" SOT-23-3_L2.9-W1.3-P1.90-LS2.4-BR 9908.08,16986.25 r0 top
Q8 "2N7002KT1G" SOT-23-3_L2.9-W1.3-P1.90-LS2.4-BR 9908.08,16421.45 r0 top
Q9 "2N7002KT1G" SOT-23-3_L2.9-W1.3-P1.90-LS2.4-BR 9370.12,15508.38 r0 top
R1 "0402WGF3741TCE" R0402 8255.26,10025.09 r0 top
R2 "HP02WAF1002TCE" R0402 8028.68,9899.82 r0 top
R3 "0201WMF1001TEE" R0201 26154.48,9516.8 r0 top
R4 "0201WMJ0330TEE" R0201 28980.43,9916.14 r0 top
R5 "0201WMJ0330TEE" R0201 28980.43,9859.69 r0 top
R6 "0201WMJ0330TEE" R0201 28980.43,9803.25 r0 top
R7 "0201WMJ0330TEE" R0201 28980.43,9746.81 r0 top
R8 "0201WMF1001TEE" R0201 21906.44,5719.15 r0 top
R9 "0201WMF1001TEE" R0201 14807.64,9733.29 r0 top
R10 "0201WMF1001TEE" R0201 20308.33,5719.15 r0 top
R11 "0201WMF1001TEE" R0201 14882.27,9733.29 r0 top
R12 "0603WAF0000T5E" R0603 29414.8,11535.39 r0 top
R13 "0603WAF0000T5E" R0603 29414.8,11617.04 r0 top
R14 "0201WMF1001TEE" R0201 12128.16,12201.83 r0 top
R15 "0201WMJ0330TEE" R0201 14250.82,9313.7 r0 top
R16 "MR04X1000FTL" R0402 11476.4,10438.43 r0 top
R17 "MR04X1000FTL" R0402 11476.4,11325.12 r0 top
R18 "0201WMF1001TEE" R0201 11601.04,11701.54 r0 top
R19 "MR04X1000FTL" R0402 11476.4,11079.43 r0 top
R20 "0201WMF1001TEE" R0201 27196.91,4511.09 r0 top
R21 "0201WMF1001TEE" R0201 27346.19,6790.36 r0 top
R22 "MR04X1000FTL" R0402 11476.4,10949.54 r0 top
R23 "0201WMF1001TEE" R0201 11526.4,11701.54 r0 top
R24 "SCR0402F100K" R0402 26681.61,8011.79 r0 top
R25 "RT0402FRE131KL" R0402 19301.06,5769.15 r0 top
R26 "0201WMJ0330TEE" R0201 28980.43,10261.1 r0 top
R27 "0201WMJ0330TEE" R0201 28980.43,10204.66 r0 top
R28 "0201WMJ0330TEE" R0201 28980.43,10148.22 r0 top
R29 "0201WMJ0330TEE" R0201 31410.31,6697.3 r0 top
R30 "0201WMJ0330TEE" R0201 19213.72,3243.85 r0 top
R31 "0201WMJ0330TEE" R0201 28980.43,10091.77 r0 top
R32 "HP02WAJ0000TCE" R0402 19126.38,7145.68 r0 top
R33 "HP02WAJ0000TCE" R0402 19301.06,7145.68 r0 top
R34 "0201WMJ0330TEE" R0201 28980.43,9690.37 r0 top
R35 "0201WMJ0330TEE" R0201 28980.43,9629.68 r0 top
R36 "RT0402FRE131KL" R0402 21530.85,5312.82 r0 top
R37 "HP02WAF1002TCE" R0402 29532.2,4841.75 r0 top
R38 "HP02WAF1002TCE" R0402 12215.5,11651.54 r0 top
R39 "0201WMF1001TEE" R0201 27271.55,6790.36 r0 top
R40 "0201WMF1001TEE" R0201 27122.27,6790.36 r0 top
R41 "MCR01MZPF4992" R0402 21430.82,12332.35 r0 top
R42 "QR0402J0R00Q10Z" R0402 21015.96,12462.24 r0 top
R43 "0201WMJ0330TEE" R0201 28980.43,9573.24 r0 top
R44 "RN731ETTP2001F25" R0402 20618.37,13267.02 r0 top
R45 "0201WMJ0330TEE" R0201 28980.43,9460.36 r0 top
R46 "0201WMJ0330TEE" R0201 28980.43,9403.92 r0 top
R47 "MCR01MZPF4992" R0402 21430.82,10591.11 r0 top
R48 "QR0402J0R00Q10Z" R0402 21015.96,10765.39 r0 top
R49 "0201WMJ0330TEE" R0201 28980.43,9347.47 r0 top
R50 "RN731ETTP2001F25" R0402 20618.37,11470.44 r0 top
R51 "0201WMJ0330TEE" R0201 28980.43,9255.41 r0 top
R52 "MCR01MZPF4992" R0402 21430.82,8285.31 r0 top
R53 "QR0402J0R00Q10Z" R0402 21015.96,8350.25 r0 top
R54 "QR0402J0R00Q10Z" R0402 21065.96,8076.73 r0 top
R55 "MCR01MZPF4992" R0402 21430.82,7946.84 r0 top
R56 "0201WMJ0330TEE" R0201 26231.69,10765.39 r0 top
R57 "0201WMJ0330TEE" R0201 26231.69,10708.95 r0 top
R58 "0805W8F1002T5E" R0805 5963.13,11812.52 r0 top
R59 "RN731ETTP2001F25" R0402 20618.37,9134.02 r0 top
R60 "0201WMF1001TEE" R0201 27346.19,4511.09 r0 top
R61 "0201WMF1001TEE" R0201 27271.55,4511.09 r0 top
R62 "0201WMF1001TEE" R0201 27122.27,4511.09 r0 top
R63 "0805W8F1002T5E" R0805 23239.53,6528.53 r0 top
R64 "0201WMF1001TEE" R0201 27420.83,4511.09 r0 top
R65 "0201WMF1001TEE" R0201 27047.63,6790.36 r0 top
R66 "0201WMF1001TEE" R0201 27420.83,6790.36 r0 top
R67 "0201WMF1001TEE" R0201 27196.91,6790.36 r0 top
R68 "CR0402F1M00Q10Z" R0402 8645.81,12092.91 r0 top
R69 "CR0402F1M00Q10Z" R0402 8645.81,12528.15 r0 top
R70 "HP02WAF1002TCE" R0402 6858.49,10541.25 r0 top
R71 "HP02WAF1002TCE" R0402 6717.13,9834.88 r0 top
R72 "HP02WAF1002TCE" R0402 7298.69,11126.27 r0 top
R73 "RC0402FR-0710KL" R0402 6958.52,12233.14 r0 top
R74 "MCR01MZPF4992" R0402 21430.82,11841.68 r0 top
R75 "QR0402J0R00Q10Z" R0402 21065.96,11906.62 r0 top
R76 "SCR0402F100K" R0402 26681.61,7440.31 r0 top
R77 "0201WMJ0330TEE" R0201 27196.91,7490.31 r0 top
R78 "MCR01MZPF4992" R0402 21430.82,9976.83 r0 top
R79 "QR0402J0R00Q10Z" R0402 21065.96,10041.77 r0 top
R80 "0201WMJ0330TEE" R0201 26231.69,10652.5 r0 top
R81 "0201WMJ0330TEE" R0201 26231.69,10530.42 r0 top
R82 "0201WMJ0330TEE" R0201 26231.69,10473.98 r0 top
R83 "0201WMJ0330TEE" R0201 26231.69,10417.54 r0 top
R84 "0201WMJ0330TEE" R0201 26231.69,10361.1 r0 top
R85 "0201WMJ0330TEE" R0201 26231.69,11344.81 r0 top
R86 "0201WMJ0330TEE" R0201 26231.69,11288.37 r0 top
R87 "0201WMJ0330TEE" R0201 26231.69,11188.37 r0 top
R88 "0201WMJ0330TEE" R0201 26231.69,11131.92 r0 top
R89 "0201WMJ0330TEE" R0201 26231.69,11031.92 r0 top
R90 "0201WMF2671TEE" R0201 12520.54,13593.59 r0 top
R91 "0201WMF2671TEE" R0201 12374.37,13593.59 r0 top
R92 "0201WMF2671TEE" R0201 13530.91,13593.59 r0 top
R93 "0201WMF2671TEE" R0201 13452.26,13593.59 r0 top
R94 "HP02WAJ0000TCE" R0402 13364.92,13078.1 r0 top
R95 "RC0201JR-070RL" R0201 12947.14,12725.91 r0 top
R96 "RC0201JR-070RL" R0201 12947.14,12669.47 r0 top
R97 "0201WMJ0330TEE" R0201 14250.82,9257.25 r0 top
R98 "0201WMJ0330TEE" R0201 14250.82,9455.18 r0 top
R99 "0201WMF2671TEE" R0201 11271.36,9792.74 r0 top
R100 "0201WMF2671TEE" R0201 11069.2,9792.74 r0 top
R101 "HP02WAF1002TCE" R0402 6858.49,9334.75 r0 top
R103 "HP02WAF1002TCE" R0402 13047.14,10213.27 r0 top
R104 "HP02WAF1002TCE" R0402 13618.25,10949.54 r0 top
R105 "0805W8F1002T5E" R0805 24335.65,4427.95 r0 top
R106 "0805W8F1002T5E" R0805 24631.81,3989.67 r0 top
R107 "MR04X1000FTL" R0402 19942.31,9194.72 r0 top
R108 "0805W8F1002T5E" R0805 23418.36,5850.57 r0 top
R109 "0805W8F1002T5E" R0805 23714.38,5197.39 r0 top
R110 "0805W8F1002T5E" R0805 24025.02,4791.75 r0 top
R111 "QR0402J0R00Q10Z" R0402 29701.78,4571.79 r0 top
R115 "MR04X1000FTL" R0402 19942.31,11535.39 r0 top
R116 "MR04X1000FTL" R0402 19942.31,13331.96 r0 top
R130 "HP02WAF1002TCE" R0402 13264.88,11762.23 r0 top
R132 "HP02WAF1002TCE" R0402 14602.59,11586.59 r0 top
R133 "RC0402FR-075K1L" R0402 3297.08,17306.6 r0 top
R134 "RC0402FR-075K1L" R0402 3038.18,16471.45 r0 top
R135 "RC0402FR-075K1L" R0402 3347.08,16251.1 r0 top
R136 "RC0402FR-075K1L" R0402 3347.08,16186.15 r0 top
R137 "RC0402FR-075K1L" R0402 5660.66,16807 r0 top
R138 "RC0402FR-075K1L" R0402 5986.48,16807 r0 top
R139 "ERA2AEB104X" R0402 5660.66,16316.04 r0 top
R140 "RT0402BRD0713K7L" R0402 5660.66,16186.15 r0 top
R141 "RC0402FR-075K1L" R0402 9620.19,17156.6 r0 top
R142 "RC0402FR-075K1L" R0402 10033.3,17156.6 r0 top
R143 "RC0402FR-075K1L" R0402 9620.19,16631.75 r0 top
R144 "RC0402FR-075K1L" R0402 10033.3,16631.75 r0 top
R145 "CRCW0402100KFKEDC" R0402 7403.65,17915.86 r0 top
R146 "RC0402FR-075K1L" R0402 7294.78,17583.01 r0 top
R147 "RC0402FR-075K1L" R0402 9611.09,17403.12 r0 top
R148 "ERA2AEB104X" R0402 8532.41,16757 r0 top
R149 "ERA2AEB104X" R0402 4648,14892.18 r0 top
R150 "ERA2AEB104X" R0402 3447.08,15840.85 r0 top
R151 "CRCW04020000Z0EDC" R0402 3596.09,15840.85 r0 top
R152 "CRCW04020000Z0EDC" R0402 5120.63,14886.78 r0 top
R153 "ERA2AEB104X" R0402 4920.56,14476.77 r0 top
R154 "CRCW04020000Z0EDC" R0402 3347.08,14026.28 r0 top
R155 "CRCW04020000Z0EDC" R0402 3088.18,14026.28 r0 top
R156 "CRCW04020000Z0EDC" R0402 4137.03,14026.28 r0 top
R157 "CRCW04020000Z0EDC" R0402 4137.03,13896.39 r0 top
R158 "CRCW04020000Z0EDC" R0402 4911.69,13164.77 r0 top
R159 "CRCW04020000Z0EDC" R0402 6249.87,15458.38 r0 top
R160 "CRCW04020000Z0EDC" R0402 6199.87,14821.83 r0 top
R161 "CRCW04020000Z0EDC" R0402 6199.87,14756.89 r0 top
R162 "CRCW0402100KFKEDC" R0402 6680.24,14380.53 r0 top
R163 "RC0402FR-075K1L" R0402 6580.24,14091.22 r0 top
R164 "RC0402FR-075K1L" R0402 5777.6,13368.46 r0 top
R165 "CRCW04021M00FKED" R0402 7185.91,13476.8 r0 top
R166 "CRCW0402330RJNED" R0402 9370.12,15765.93 r0 top
R167 "CRCW0402330RJNED" R0402 9215.6,15765.93 r0 top
R168 "CRCW0402330RJNED" R0402 8218.51,15508.38 r0 top
R169 "CRCW0402330RJNED" R0402 8318.55,15508.38 r0 top
R170 "CRCW0402330RJNED" R0402 9061.09,15508.38 r0 top
R171 "ERA2AEB104X" R0402 9215.6,15508.38 r0 top
S1 "CHS-01TA1" SW-SMD_2P-L5.4-W2.5-LS5.6 6425.78,12528.15 r0 top
S2 "SS12D07VG4 087" SW-TH_SS12D07VG4 26481.61,7808.98 r0 top
S3 "1-1825010-3" SW_1-1825010-3 10516.8,11090.07 r0 top
S5 "FSM6JSMA" SW-SMD_4P-L6.0-W6.0-P4.50-LS10.0-BL 19577.45,5147.39 r0 top
S6 "CHS-01TA1" SW-SMD_2P-L5.4-W2.5-LS5.6 6525.78,9496.53 r0 top
S8 "219-2LPST" SW-SMD_CTS_219-2LPST 27952.42,3436.91 r0 top
S9 "TS3643TP" KEY-SMD_L6.0-W3.5-LS8.4 27902.42,5512.82 r0 top
S10 "TS3643TP" KEY-SMD_L6.0-W3.5-LS8.4 27902.42,5262.82 r0 top
S11 "TS3643TP" KEY-SMD_L6.0-W3.5-LS8.4 27952.42,4200.89 r0 top
S12 "219-2LPST" SW-SMD_CTS_219-2LPST 27952.42,3889.67 r0 top
S13 "TS3643TP" KEY-SMD_L6.0-W3.5-LS8.4 27902.42,6389.74 r0 top
S14 "TS3643TP" KEY-SMD_L6.0-W3.5-LS8.4 27902.42,6154.47 r0 top
S15 "TS3643TP" KEY-SMD_L6.0-W3.5-LS8.4 27902.42,5900.57 r0 top
S16 "TS3643TP" KEY-SMD_L6.0-W3.5-LS8.4 27902.42,5669.15 r0 top
S17 "CHS-01TA1" SW-SMD_2P-L5.4-W2.5-LS5.6 13630.91,10213.27 r0 top
S18 "CHS-01TA1" SW-SMD_2P-L5.4-W2.5-LS5.6 6325.78,10025.09 r0 top
S19 "CHS-01TA1" SW-SMD_2P-L5.4-W2.5-LS5.6 6908.49,11287.47 r0 top
S20 "CHS-01TA1" SW-SMD_2P-L5.4-W2.5-LS5.6 6425.78,10722.12 r0 top
S21 "219-2LPST" SW-SMD_CTS_219-2LPST 11576.4,11947.23 r0 top
SJ1 "IOVDD_1797" HDR-TH_2P-P2.54-V-M 3257.66,13467.24 r0 top
TP1 "SCL_1797" TESTPOINT-TH_BD3.2 11651.04,12967.8 r0 top
TP2 "SDA_1797" TESTPOINT-TH_BD3.2 11895.3,12967.8 r0 top
TP3 "IIC0_SCL" TESTPOINT-TH_BD3.2 10356.15,16631.75 r0 top
TP4 "IIC0_SDA" TESTPOINT-TH_BD3.2 5307.32,15665.93 r0 top
TP5 "RH-5002" TESTPOINT-TH_BD2.5-D1.2_RH-5002 28383.87,13494.22 r0 top
TP6 "LOVE" TESTPOINT-TH_BD3.2 5407.32,16581.75 r0 top
TP7 "MD" TESTPOINT-TH_BD3.2 10356.15,17156.6 r0 top
TP8 "VUBS_CONN" TESTPOINT-TH_BD3.2 3065.99,13608.92 r0 top
U1 "ADAU1797" ADAU1797_WLCSP_CB-77-1 28105.19,10441.11 r0 top
U2 "MX25U3232FM2I02" SOIC-8_L5.3-W5.3-P1.27-LS8.0-BL 30156.93,4421.79 r0 top
U3 "ADP1715ARMZ-R7" MSOP-8_L3.0-W3.0-P0.65-LS4.9-BL 7348.69,10125.09 r0 top
U4 "TXB0108DQSR" SON-20_L4.0-W2.0-P0.40-BL 4920.56,14541.72 r0 top
U5 "SN74AUC1G07DCKR" SC-70-5_L2.0-W1.3-P0.65-LS2.1-BR 20965.96,5412.82 r0 top
U6 "ADP3335ARM-1.8-RL" MSOP-8_L3.0-W3.0-P0.65-LS4.9-BL 7789.99,11337.47 r0 top
U7 "FXLH1T45L6X" SIP-6_L1.5-W1.0-P0.50-BL 17486.09,11847.86 r0 top
U8 "ADP1713AUJZ-1.2-R7" TSOT-5_L2.9-W1.6-P0.95-LS2.8-BR 7398.69,10822.12 r0 top
U10 "FXLH1T45L6X" SIP-6_L1.5-W1.0-P0.50-BL 17486.09,12413.09 r0 top
U11 "74AVCH1T45GW,125" SC-88-6_L2.0-W1.3-P0.65-LS2.1-BL 12743.65,10536.62 r0 top
U12 "PCA9617ADMR2G" SOIC-8_L3.0-W3.0-P0.65-LS4.9-BL 12897.14,13375.42 r0 top
U16 "LT1761ES5-5#TRPBF" TSOT-23-5_L2.9-W1.6-P0.95-LS2.8-BR 7548.69,9596.53 r0 top
U17 "ADP5302-ACPZ-1" LFCSP-10_L3.0-W3.0-P0.50-BL-EP-1 7839.99,12414.03 r0 top
U18 "SN74AVC4T245PWR" TSSOP-16_L5.0-W4.4-P0.65-LS6.4-BL 12693.65,11551.54 r0 top
U20 "FXLH1T45L6X" SIP-6_L1.5-W1.0-P0.50-BL 17486.09,11129.43 r0 top
U21 "FXLH1T45L6X" SIP-6_L1.5-W1.0-P0.50-BL 17486.09,9939.06 r0 top
U22 "R7FA4M1AB3CFM#AA0" LQFP-64_L10.0-W10.0-P0.50-LS12.0-BL 3265.74,18468.03 r0 top
U23 "CC0402KRX7R6BB474" C0402 8168.51,17256.6 r0 top
U24 "PRTR5V0U2X-ES" SOT-143_L2.9-W1.3-P1.92-LS2.3-BR 7135.91,14284.28 r0 top
U25 "TPNLASB3157DFT2G" SOT-363-6_L2.0-W1.3-P0.65-LS2.3-BL 6199.87,14597.85 r0 top
U26 "TPNLASB3157DFT2G" SOT-363-6_L2.0-W1.3-P0.65-LS2.3-BL 5554.99,14380.53 r0 top
U-LEDMATRIX1 "HB-PH3-254111PB2GOP" HDR-TH_11P-P2.54-V-M 8568.51,14187.75 r0 top
Y1 "ASFLMB-24.576MHZ-LR-T" OSC-SMD_4P-L5.0-W3.2-BL_ASFLMB 24731.81,9205.41 r0 top
Y2 "H1OEL89CSC-SUGYLC-24.576M" HC-49US_L11.5-W4.5-P4.88 26154.48,8998.11 r0 top

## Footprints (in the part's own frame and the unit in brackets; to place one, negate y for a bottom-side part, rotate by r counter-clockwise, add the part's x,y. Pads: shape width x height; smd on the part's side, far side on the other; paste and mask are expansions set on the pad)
ADAU1797_WLCSP_CB-77-1 [mm]
  round 0.26 smd far side: A1(0,4)
  round 0.249 smd far side: A2(0.4,4) A3(0.8,4) A4(1.2,4) A5(1.6,4) A6(2,4) A7(2.4,4) B1(0,3.6) B2(0.4,3.6) B3(0.8,3.6) B4(1.2,3.6) B5(1.6,3.6) B6(2,3.6) B7(2.4,3.6) C1(0,3.2) C2(0.4,3.2) C3(0.8,3.2) C4(1.2,3.2) C5(1.6,3.2) C6(2,3.2) C7(2.4,3.2) D1(0,2.8) D2(0.4,2.8) D3(0.8,2.8) D4(1.2,2.8) D5(1.6,2.8) D6(2,2.8) D7(2.4,2.8) E1(0,2.4) E2(0.4,2.4) E3(0.8,2.4) E4(1.2,2.4) E5(1.6,2.4) E6(2,2.4) E7(2.4,2.4) F1(0,2) F2(0.4,2) F3(0.8,2) F4(1.2,2) F5(1.6,2) F6(2,2) F7(2.4,2) G1(0,1.6) G2(0.4,1.6) G3(0.8,1.6) G4(1.2,1.6) G5(1.6,1.6) G6(2,1.6) G7(2.4,1.6) H1(0,1.2) H2(0.4,1.2) H3(0.8,1.2) H4(1.2,1.2) H5(1.6,1.2) H6(2,1.2) H7(2.4,1.2) J1(0,0.8) J2(0.4,0.8) J3(0.8,0.8) J4(1.2,0.8) J5(1.6,0.8) J6(2,0.8) J7(2.4,0.8) K1(0,0.4) K2(0.4,0.4) K3(0.8,0.4) K4(1.2,0.4) K5(1.6,0.4) K6(2,0.4) K7(2.4,0.4) L1(0,0) L2(0.4,0) L3(0.8,0) L4(1.2,0) L5(1.6,0) L6(2,0) L7(2.4,0)
  Top Layer region: -0.413,4.4 2.827,4.4 2.827,-0.426 -0.413,-0.426
  silkscreen extent -0.31,3.89 0.05,4.24
AUDIO-SMD_SJ-3523-SMT-TR [mm]
  rect 2.2x2.8 smd: 1(-4.7,-3.7) 3(-2.7,3.7)
  rect 2.8x2.8 smd: 2(4.7,-3.7)
  Board Outline Layer circle w0.005: c-3.6,0 r0.85
  Board Outline Layer circle w0.005: c3.4,0 r0.85
  Board Outline Layer region: -2.75,0 -2.834,-0.369 -3.07,-0.665 -3.411,-0.829 -3.789,-0.829 -4.13,-0.665 -4.366,-0.369 -4.45,0 -4.45,0 -4.366,0.369 -4.13,0.665 -3.789,0.829 -3.411,0.829 -3.07,0.665 -2.834,0.369 -2.75,0
  Board Outline Layer region: 4.25,0 4.166,-0.369 3.93,-0.665 3.589,-0.829 3.211,-0.829 2.87,-0.665 2.634,-0.369 2.55,0 2.55,0 2.634,0.369 2.87,0.665 3.211,0.829 3.589,0.829 3.93,0.665 4.166,0.369 4.25,0
  Multi-Layer board cut-out: -2.75,0 -2.834,-0.369 -3.07,-0.665 -3.411,-0.829 -3.789,-0.829 -4.13,-0.665 -4.366,-0.369 -4.45,0 -4.45,0 -4.366,0.369 -4.13,0.665 -3.789,0.829 -3.411,0.829 -3.07,0.665 -2.834,0.369 -2.75,0
  Multi-Layer board cut-out: 4.25,0 4.166,-0.369 3.93,-0.665 3.589,-0.829 3.211,-0.829 2.87,-0.665 2.634,-0.369 2.55,0 2.55,0 2.634,0.369 2.87,0.665 3.211,0.829 3.589,0.829 3.93,0.665 4.166,0.369 4.25,0
  silkscreen extent -9.6,-3 7.4,3
BULETM-SMD_ESP32-S3-MINI-1-N8 [mm]
  rect 0.8x0.4 smd: 1(-6.975,5.95) 2(-6.975,5.1) 3(-6.975,4.25) 4(-6.975,3.4) 5(-6.975,2.55) 6(-6.975,1.7) 7(-6.975,0.85) 8(-6.975,0) 9(-6.975,-0.85) 10(-6.975,-1.7) 11(-6.975,-2.55) 12(-6.975,-3.4) 13(-6.975,-4.25) 14(-6.975,-5.1) 15(-6.975,-5.95) 31(6.975,-5.95) 32(6.975,-5.1) 33(6.975,-4.25) 34(6.975,-3.4) 35(6.975,-2.55) 36(6.975,-1.7) 37(6.975,-0.85) 38(6.975,0) 39(6.975,0.85) 40(6.975,1.7) 41(6.975,2.55) 42(6.975,3.4) 43(6.975,4.25) 44(6.975,5.1) 45(6.975,5.95)
  rect 0.4x0.8 smd: 16(-5.95,-7.025) 17(-5.1,-7.025) 18(-4.25,-7.025) 19(-3.4,-7.025) 20(-2.55,-7.025) 21(-1.7,-7.025) 22(-0.85,-7.025) 23(0,-7.025) 24(0.85,-7.025) 25(1.7,-7.025) 26(2.55,-7.025) 27(3.4,-7.025) 28(4.25,-7.025) 29(5.1,-7.025) 30(5.95,-7.025) 46(5.95,7.025) 47(5.1,7.025) 48(4.25,7.025) 49(3.4,7.025) 50(2.55,7.025) 51(1.7,7.025) 52(0.85,7.025) 53(0,7.025) 54(-0.85,7.025) 55(-1.7,7.025) 56(-2.55,7.025) 57(-3.4,7.025) 58(-4.25,7.025) 59(-5.1,7.025) 60(-5.95,7.025)
  rect 0.8x0.8 smd: GND(-7,-7) GND(-7,7) GND(7,-7) GND(7,7)
  rect 1.2x1.2 smd: GND(-1.65,-1.65) GND(-1.65,0) GND(-1.65,1.65) GND(0,-1.65) GND(0,0) GND(0,1.65) GND(1.65,-1.65) GND(1.65,0) GND(1.65,1.65)
  silkscreen extent -8.34,-7.7 7.8,12.8
C0201 [mil]
  rect 14.51x12.76 smd: 1(-10.8,0) 2(10.8,0)
  silkscreen extent -27,-15 27,15
C0402 [mm]
  rect 0.79x0.54 smd: 1(-0.545,0) 2(0.545,0)
  silkscreen extent -1.17,-0.5 1.17,0.5
C0603 [mm]
  rect 0.8x0.9 smd: 1(-0.7,0) 2(0.7,0)
  silkscreen extent -1.39,-0.71 1.39,0.71
C0805 [mm]
  rect 1.41x1.35 smd: 1(-1,0) 2(1,0)
  silkscreen extent -1.96,-0.9 1.96,0.9
CONN34_878313420_MOL [mil]
  round 57 hole 37: 1(0,0) 2(0,78.74) 3(78.74,0) 4(78.74,78.74) 5(157.48,0) 6(157.48,78.74) 7(236.22,0) 8(236.22,78.74) 9(314.96,0) 10(314.96,78.74) 11(393.7,0) 12(393.7,78.74) 13(472.44,0) 14(472.44,78.74) 15(551.18,0) 16(551.18,78.74) 17(629.92,0) 18(629.92,78.74) 19(708.66,0) 20(708.66,78.74) 21(787.4,0) 22(787.4,78.74) 23(866.14,0) 24(866.14,78.74) 25(944.88,0) 26(944.88,78.74) 27(1023.62,0) 28(1023.62,78.74) 29(1102.36,0) 30(1102.36,78.74) 31(1181.1,0) 32(1181.1,78.74) 33(1259.84,0) 34(1259.84,78.74)
  silkscreen extent -147,-90 1356,168
CONN-SMD_4P-P1.00_SM04B-SRSS-TB-LF-SN [mm]
  rect 0.6x1.55 smd: 1(-1.5,1.938) 2(-0.5,1.938) 3(0.5,1.938) 4(1.5,1.938)
  rect 1.2x1.8 smd: 5(2.8,-1.938) 6(-2.8,-1.938)
  silkscreen extent -3.02,-2.46 2.96,1.8
CONN-TH_24.243.1_RED [mm]
  round 3 hole 2: 1(-7.85,0) 2(7.85,0)
  silkscreen extent -11.35,-5.05 12.65,5.65
CONN-TH_24.243.2 [mm]
  round 3 hole 2: 1(-7.85,0) 2(7.85,0)
  silkscreen extent -11.35,-5.05 12.65,5.65
DC-IN-TH_DC-509-ARL200-H142 [mm]
  oval 3.6x1.6 hole 0.8 slot 3 at 0 deg: 3(-1.75,-3.15) 4(1.75,-1.9) 5(-1.75,3.15)
  silkscreen extent -6.25,-6.1 2.75,4.9
F1812 [mil]
  rect 55.38x137.76 smd: 1(-72.97,0) 2(72.97,0)
  silkscreen extent -110,-80 110,80
HC-49US_L11.5-W4.5-P4.88 [mm]
  rect 1.5x1.5 hole 0.9: 1(-2.44,0)
  round 1.5 hole 0.9: 2(2.44,0)
  silkscreen extent -5.39,-2.25 5.39,2.25
HDR-TH_2P-P2.54-V-M [mm]
  rect 2x2 hole 1.2: 1(-1.27,0)
  round 2 hole 1.2: 2(1.27,0)
  silkscreen extent -2.54,-1.27 2.54,1.27
HDR-TH_3P-P2.54-V-M [mm]
  rect 1.7x1.7 hole 1.1: 1(-2.54,0)
  round 1.7 hole 1.1: 2(0,0) 3(2.54,0)
  silkscreen extent -3.81,-1.25 3.81,1.25
HDR-TH_4P-P2.54-V-M-R2-C2-S2.54 [mm]
  rect 1.7x1.7 hole 1.1: 1(-1.27,-1.27)
  round 1.7 hole 1.1: 2(-1.27,1.27) 3(1.27,-1.27) 4(1.27,1.27)
  silkscreen extent -2.77,-2.54 2.77,2.54
HDR-TH_6P-P2.54-V-F [mm]
  rect 1.8x1.8 hole 1.02: 1(-6.35,0)
  round 1.6 hole 1.02: 2(-3.81,0) 3(-1.27,0) 4(1.27,0) 5(3.81,0) 6(6.35,0)
  silkscreen extent -7.87,-1.25 7.87,1.25
HDR-TH_6P-P2.54-V-M-R2-C3-S2.54 [mm]
  rect 1.7x1.7 hole 1.1: 1(-2.54,-1.27)
  round 1.7 hole 1.1: 2(-2.54,1.27) 3(0,-1.27) 4(0,1.27) 5(2.54,-1.27) 6(2.54,1.27)
  silkscreen extent -4.04,-2.54 4.04,2.54
HDR-TH_6P-P2.54-V-M-R2-C3-S2.54-1 [mm]
  rect 1.8x1.8 hole 1.05: 1(-2.54,-1.27)
  round 1.8 hole 1.05: 2(-2.54,1.27) 3(0,-1.27) 4(0,1.27) 5(2.54,-1.27) 6(2.54,1.27)
  silkscreen extent -3.81,-2.54 3.81,2.54
HDR-TH_8P-P2.54-V-M-R2-C4-S2.54 [mm]
  rect 1.7x1.7 hole 1.1: 1(-3.81,-1.27)
  round 1.7 hole 1.1: 2(-3.81,1.27) 3(-1.27,-1.27) 4(-1.27,1.27) 5(1.27,-1.27) 6(1.27,1.27) 7(3.81,-1.27) 8(3.81,1.27)
  silkscreen extent -5.08,-2.54 5.08,2.54
HDR-TH_10P-P2.54-V-M-R2-C5-S2.54 [mm]
  rect 1.7x1.7 hole 1.1: 1(-5.08,-1.27)
  round 1.7 hole 1.1: 2(-5.08,1.27) 3(-2.54,-1.27) 4(-2.54,1.27) 5(0,-1.27) 6(0,1.27) 7(2.54,-1.27) 8(2.54,1.27) 9(5.08,-1.27) 10(5.08,1.27)
  silkscreen extent -6.35,-2.54 6.35,2.54
HDR-TH_11P-P2.54-V-M [mm]
  rect 1.6x1.6 hole 1.05: 1(-12.7,0)
  round 1.6 hole 1.05: 2(-10.16,0) 3(-7.62,0) 4(-5.08,0) 5(-2.54,0) 6(0,0) 7(2.54,0) 8(5.08,0) 9(7.62,0) 10(10.16,0) 11(12.7,0)
  silkscreen extent -13.97,-1.25 13.97,1.25
HDR-TH_14P-P2.54-V-M [mm]
  rect 1.8x1.8 hole 1.1: 1(-16.51,0)
  round 1.8 hole 1.1: 2(-13.97,0) 3(-11.43,0) 4(-8.89,0) 5(-6.35,0) 6(-3.81,0) 7(-1.27,0) 8(1.27,0) 9(3.81,0) 10(6.35,0) 11(8.89,0) 12(11.43,0) 13(13.97,0) 14(16.51,0)
  silkscreen extent -17.78,-1.25 17.78,1.25
HDR-TH_16P-P2.54-V-M-R2-C8-S2.54 [mm]
  rect 1.8x1.8 hole 1.2: 1(-8.89,-1.27)
  round 1.8 hole 1.2: 2(-8.89,1.27) 3(-6.35,-1.27) 4(-6.35,1.27) 5(-3.81,-1.27) 6(-3.81,1.27) 7(-1.27,-1.27) 8(-1.27,1.27) 9(1.27,-1.27) 10(1.27,1.27) 11(3.81,-1.27) 12(3.81,1.27) 13(6.35,-1.27) 14(6.35,1.27) 15(8.89,-1.27) 16(8.89,1.27)
  silkscreen extent -10.16,-2.5 10.16,2.5
HDR-TH_18P-P2.54-V-M [mm]
  rect 1.65x1.6 hole 1.1: 1(-21.59,0)
  round 1.65 hole 1.1: 2(-19.05,0) 3(-16.51,0) 4(-13.97,0) 5(-11.43,0) 6(-8.89,0) 7(-6.35,0) 8(-3.81,0) 9(-1.27,0) 10(1.27,0) 11(3.81,0) 12(6.35,0) 13(8.89,0) 14(11.43,0) 15(13.97,0) 16(16.51,0) 17(19.05,0) 18(21.59,0)
  silkscreen extent -22.86,-1.25 22.86,1.25
IDC-TH_20P-P2.54_3M_N2520-6002-RB [mm]
  rect 1.8x1.8 hole 1.1: 1(-11.43,-1.27)
  round 1.8 hole 1.1: 2(-11.43,1.27) 3(-8.89,-1.27) 4(-8.89,1.27) 5(-6.35,-1.27) 6(-6.35,1.27) 7(-3.81,-1.27) 8(-3.81,1.27) 9(-1.27,-1.27) 10(-1.27,1.27) 11(1.27,-1.27) 12(1.27,1.27) 13(3.81,-1.27) 14(3.81,1.27) 15(6.35,-1.27) 16(6.35,1.27) 17(8.89,-1.27) 18(8.89,1.27) 19(11.43,-1.27) 20(11.43,1.27)
  silkscreen extent -16.5,-5.84 16.5,4.7
KEY-SMD_L6.0-W3.5-LS8.4 [mm]
  rect 1.8x1.524 smd: 1(-3.85,0) 2(3.85,0)
  silkscreen extent -3,-1.78 3,1.91
L0603 [mm]
  rect 0.8x0.864 smd: 1(-0.7,0) 2(0.7,0)
  silkscreen extent -1.42,-0.65 1.42,0.65
L1210 [mm]
  rect 1.474x2.22 smd: 1(-1.703,0) 2(1.703,0)
  silkscreen extent -2.67,-1.4 2.67,1.4
LED1206-R-RD_GREEN [mm]
  rect 1.485x1.62 smd: 1(1.493,0) 2(-1.492,0)
  silkscreen extent -2.77,-1.04 2.46,1.04
LED1206-RD [mm]
  rect 1.635x1.6 smd: 1(-1.517,0) 2(1.517,0)
  silkscreen extent -2.99,-1.04 2.57,1.07
LED-SMD_L1.6-W0.8-R-RD [mm]
  rect 0.8x0.8 smd: 1(0.75,0) 2(-0.75,0)
  silkscreen extent -1.7,-0.7 1.47,0.7
LED-SMD_L1.6-W0.8-RD [mm]
  rect 0.8x0.8 smd: 1(-0.75,0) 2(0.75,0)
  silkscreen extent -1.7,-0.7 1.47,0.7
LFCSP-10_L3.0-W3.0-P0.50-BL-EP-1 [mm]
  oval 0.3x0.8 smd: 1(-1,-1.424) 2(-0.5,-1.424) 3(0,-1.424) 4(0.5,-1.424) 5(1,-1.424) 6(1,1.424) 7(0.5,1.424) 8(0,1.424) 9(-0.5,1.424) 10(-1,1.424)
  rect 2.38x1.64 smd: 11(0,0)
  silkscreen extent -1.78,-2.16 1.65,1.52
LQFP-64_L10.0-W10.0-P0.50-LS12.0-BL [mm]
  oval 0.3x2 smd: 1(-3.75,-5.75) 2(-3.25,-5.75) 3(-2.75,-5.75) 4(-2.25,-5.75) 5(-1.75,-5.75) 6(-1.25,-5.75) 7(-0.75,-5.75) 8(-0.25,-5.75) 9(0.25,-5.75) 10(0.75,-5.75) 11(1.25,-5.75) 12(1.75,-5.75) 13(2.25,-5.75) 14(2.75,-5.75) 15(3.25,-5.75) 16(3.75,-5.75) 33(3.75,5.75) 34(3.25,5.75) 35(2.75,5.75) 36(2.25,5.75) 37(1.75,5.75) 38(1.25,5.75) 39(0.75,5.75) 40(0.25,5.75) 41(-0.25,5.75) 42(-0.75,5.75) 43(-1.25,5.75) 44(-1.75,5.75) 45(-2.25,5.75) 46(-2.75,5.75) 47(-3.25,5.75) 48(-3.75,5.75)
  oval 2x0.3 smd: 17(5.75,-3.75) 18(5.75,-3.25) 19(5.75,-2.75) 20(5.75,-2.25) 21(5.75,-1.75) 22(5.75,-1.25) 23(5.75,-0.75) 24(5.75,-0.25) 25(5.75,0.25) 26(5.75,0.75) 27(5.75,1.25) 28(5.75,1.75) 29(5.75,2.25) 30(5.75,2.75) 31(5.75,3.25) 32(5.75,3.75) 49(-5.75,3.75) 50(-5.75,3.25) 51(-5.75,2.75) 52(-5.75,2.25) 53(-5.75,1.75) 54(-5.75,1.25) 55(-5.75,0.75) 56(-5.75,0.25) 57(-5.75,-0.25) 58(-5.75,-0.75) 59(-5.75,-1.25) 60(-5.75,-1.75) 61(-5.75,-2.25) 62(-5.75,-2.75) 63(-5.75,-3.25) 64(-5.75,-3.75)
  silkscreen extent -5,-5.79 5,5
MSOP-8_L3.0-W3.0-P0.65-LS4.9-BL [mil]
  rect 15.98x55 smd: 1(-38.39,-90.55) 2(-12.8,-90.55) 3(12.8,-90.55) 4(38.39,-90.55) 5(38.39,90.55) 6(12.8,90.55) 7(-12.8,90.55) 8(-38.39,90.55)
  silkscreen extent -70,-91 59,51
OSC-SMD_4P-L5.0-W3.2-BL_ASFLMB [mm]
  rect 1.6x1.6 smd: 1(-1.27,-1.1) 2(1.27,-1.1) 3(1.27,1.1) 4(-1.27,1.1)
  silkscreen extent -2.69,-2.33 2.54,1.52
R0201 [mil]
  rect 11.93x12.76 smd: 1(-9.51,0) 2(9.51,0)
  silkscreen extent -24,-15 24,15
R0402 [mm]
  rect 0.566x0.54 smd: 1(-0.433,0) 2(0.433,0)
  silkscreen extent -0.94,-0.5 0.94,0.5
R0603 [mil]
  rect 31.75x34.02 smd: 1(-29.66,0) 2(29.66,0)
  silkscreen extent -55,-26 55,26
R0805 [mm]
  rect 1.133x1.377 smd: 1(-1,0) 2(1,0)
  silkscreen extent -1.76,-0.92 1.76,0.92
SC-70-5_L2.0-W1.3-P0.65-LS2.1-BR [mm]
  rect 0.85x0.35 smd: 1(1.1,-0.65) 2(1.1,0) 3(1.1,0.65) 4(-1.1,0.65) 5(-1.1,-0.65)
  silkscreen extent -0.5,-1.12 0.96,1
SC-75-3_L1.6-W0.8-P1.00-LS1.7-BR [mm]
  rect 0.585x0.301 smd: 1(0.643,-0.5) 2(0.643,0.5) 3(-0.643,0)
  silkscreen extent -0.38,-0.83 0.38,0.76
SC-88-6_L2.0-W1.3-P0.65-LS2.1-BL [mm]
  rect 0.4x0.8 smd: 1(-0.65,-0.95) 2(0,-0.95) 3(0.65,-0.95) 4(0.65,0.95) 5(0,0.95) 6(-0.65,0.95)
  silkscreen extent -1.42,-1.27 1.1,0.7
SIP-6_L1.5-W1.0-P0.50-BL [mm]
  rect 0.3x0.52 smd: 1(-0.5,-0.385) 2(0,-0.385) 3(0.5,-0.385) 4(0.5,0.385) 5(0,0.385) 6(-0.5,0.385)
  silkscreen extent -0.8,-1 0.8,0.58
SOD-123_L2.6-W1.7-LS3.5-RD [mm]
  rect 0.9x1 smd: 1(-1.692,0) 2(1.692,0)
  silkscreen extent -1.63,-0.94 1.41,0.94
SOD-123_L2.7-W1.6-LS3.7-RD-1 [mm]
  rect 1.2x0.95 smd: 1(-1.7,0) 2(1.7,0)
  silkscreen extent -1.81,-0.98 1.35,0.98
SOIC-8_L3.0-W3.0-P0.65-LS4.9-BL [mm]
  oval 0.45x1.45 smd: 1(-1.05,-2.2) 2(-0.35,-2.2) 3(0.35,-2.2) 4(1.05,-2.2) 5(1.05,2.2) 6(0.35,2.2) 7(-0.35,2.2) 8(-1.05,2.2)
  silkscreen extent -2.04,-2.45 1.5,1.5
SOIC-8_L5.3-W5.3-P1.27-LS8.0-BL [mm]
  oval 0.63x2.25 smd: 1(-1.905,-3.53) 2(-0.635,-3.53) 3(0.635,-3.53) 4(1.905,-3.53) 5(1.905,3.53) 6(0.635,3.53) 7(-0.635,3.53) 8(-1.905,3.53)
  silkscreen extent -2.82,-3.68 2.64,2.18
SON-20_L4.0-W2.0-P0.40-BL [mm]
  rect 0.2x1.1 smd: 1(-1.8,-0.85)
  rect 0.2x1 smd: 2(-1.4,-0.9) 3(-1,-0.9) 4(-0.6,-0.9) 5(-0.2,-0.9) 6(0.2,-0.9) 7(0.6,-0.9) 8(1,-0.9) 9(1.4,-0.9) 10(1.8,-0.9) 11(1.8,0.9) 12(1.4,0.9) 13(1,0.9) 14(0.6,0.9) 15(0.2,0.9) 16(-0.2,0.9) 17(-0.6,0.9) 18(-1,0.9) 19(-1.4,0.9) 20(-1.8,0.9)
  silkscreen extent -2.16,-2.03 2.16,1.14
SOT-23-3_L2.9-W1.3-P1.90-LS2.4-BR [mm]
  rect 1.25x0.7 smd: 1(1,-0.95) 2(1,0.95) 3(-1,0)
  silkscreen extent -0.73,-1.53 0.73,1.53
SOT-143_L2.9-W1.3-P1.92-LS2.3-BR [mm]
  rect 0.7x1.1 smd: 1(1.1,-0.75)
  rect 0.7x0.6 smd: 2(1.1,0.95) 3(-1.1,0.95) 4(-1.1,-0.95)
  silkscreen extent -0.7,-1.91 1.4,1.55
SOT-363-6_L2.0-W1.3-P0.65-LS2.3-BL [mm]
  rect 0.4x0.8 smd: 1(-0.65,-0.97) 2(0,-0.97) 3(0.65,-0.97) 4(0.65,0.97) 5(0,0.97) 6(-0.65,0.97)
  silkscreen extent -1.4,-1.14 1.1,0.65
SW-SMD_2P-L5.4-W2.5-LS5.6 [mm]
  rect 1.6x1 smd: 1(-2.54,0) 2(2.54,0)
  silkscreen extent -2.67,-1.27 2.67,1.27
SW-SMD_4P-L6.0-W6.0-P4.50-LS10.0-BL [mm]
  rect 2.2x1.5 smd: 1(-4.4,-2.25) 2(4.4,-2.25) 3(-4.4,2.25) 4(4.4,2.25)
  silkscreen extent -3,-3 3,3
SW-SMD_CTS_219-2LPST [mm]
  rect 1.13x2.44 smd: 1(-1.27,-4.28) 2(1.27,-4.28) 3(1.27,4.28) 4(-1.27,4.28)
  silkscreen extent -3.32,-3.5 3.32,3.5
